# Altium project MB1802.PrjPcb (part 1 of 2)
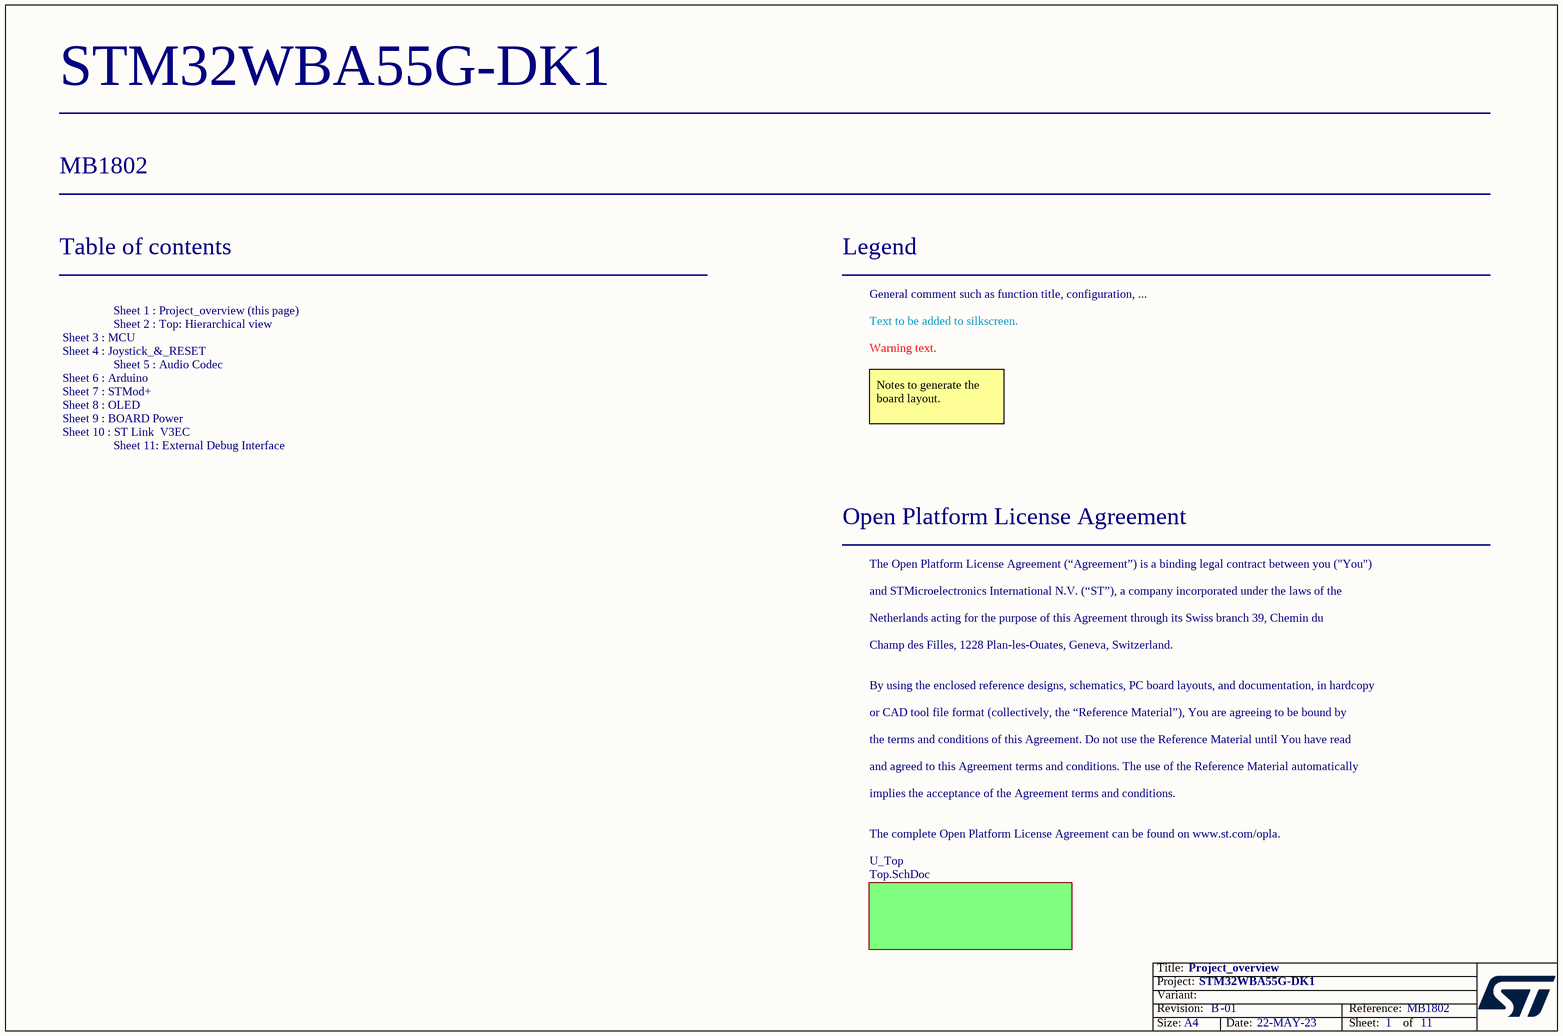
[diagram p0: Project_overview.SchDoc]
Board_Assembly_Revision: 01; Board_Document_Date: 22-MAY-23; Board_Name: STM32WBA55G-DK1; Board_PCB_Revision: B; Board_Reference: MB1802
11 sheets, 218 parts. Net scope: flat (ports and power ports of the same name join across sheets).
Board file: MB1802.PcbDoc
Sheets:
  Project_overview.SchDoc
    U_Top = Top.SchDoc
      U_Board_Power = Board_Power.SchDoc
      U_External_Debug_Interface = External_Debug_Interface.SchDoc
      U_OLED = OLED.SchDoc
      U_STLink_V3EC = STLink_V3EC.SchDoc
      U_MCU = MCU.SchDoc
      U_STMod+ = STMod+.SchDoc
      U_Audio_Codec = Audio_Codec.SchDoc
      U_Joystick_&_Reset = Joystick_&_Reset.SchDoc
      U_Arduino = Arduino.SchDoc

## Sheet Project_overview.SchDoc: Project_overview
size A4; Date: Not used; ApprovedBy: Not used; CheckedBy: Not used; Author: Not used; CompanyName: STMicroelectronics; DrawnBy: Not used; Engineer: Not used; Organization: Not used; Address1: Not used; Address2: Not used; Address3: Not used; Address4: Not used; DocumentNumber: 1; Revision: Not used; SheetNumber: 1; SheetTotal: 11

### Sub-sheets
U_Top = Top.SchDoc: no entries

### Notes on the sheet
- Table of contents
- Legend
- General comment such as function title, configuration, ...
- Text to be added to silkscreen.
- Warning text.
- Notes to generate the board layout.
- Open Platform License Agreement
- The Open Platform License Agreement (“Agreement”) is a binding legal contract between you ("You")
- and STMicroelectronics International N.V. (“ST”), a company incorporated under the laws of the
- Netherlands acting for the purpose of this Agreement through its Swiss branch 39, Chemin du
- Champ des Filles, 1228 Plan-les-Ouates, Geneva, Switzerland.
- Sheet 1 : Project_overview (this page)
  Sheet 2 : Top: Hierarchical view
  Sheet 3 : MCU
  Sheet 4 : Joystick_&_RESET
  Sheet 5 : Audio Codec
  Sheet 6 : Arduino
  Sheet 7 : STMod+
  Sheet 8 : OLED
  Sheet 9 : BOARD Power
  Sheet 10 : ST Link  V3EC
  Sheet 11: External Debug Interface
- By using the enclosed reference designs, schematics, PC board layouts, and documentation, in hardcopy
- or CAD tool file format (collectively, the “Reference Material”), You are agreeing to be bound by
- the terms and conditions of this Agreement. Do not use the Reference Material until You have read
- and agreed to this Agreement terms and conditions. The use of the Reference Material automatically
- implies the acceptance of the Agreement terms and conditions.
- The complete Open Platform License Agreement can be found on www.st.com/opla.

## Sheet Top.SchDoc: Top
size A4; Date: Not used; ApprovedBy: Not used; CheckedBy: Not used; Author: Not used; CompanyName: STMicroelectronics; DrawnBy: Not used; Engineer: Not used; Organization: Not used; Address1: Not used; Address2: Not used; Address3: Not used; Address4: Not used; DocumentNumber: Not used; Revision: Not used; SheetNumber: 2; SheetTotal: 11
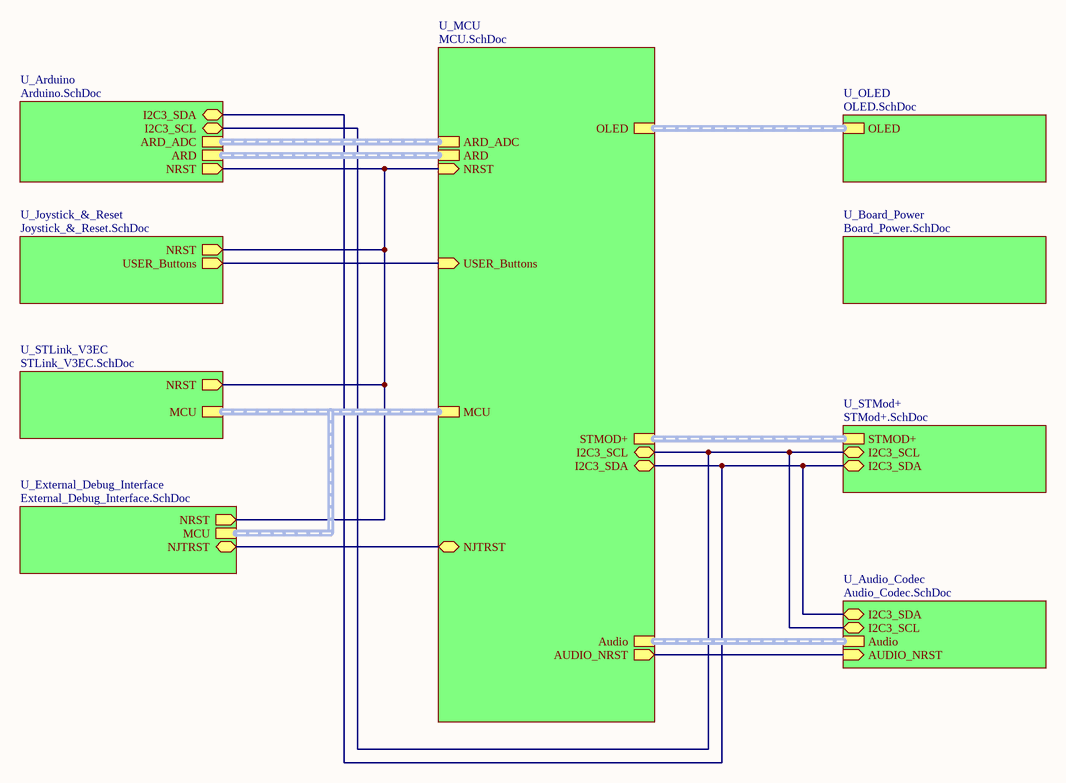
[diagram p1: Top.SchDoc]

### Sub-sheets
U_Arduino = Arduino.SchDoc: NRST (out), I2C3_SDA (bidir), I2C3_SCL (bidir), ARD (harness ARD), ARD_ADC (harness ARD_ADC)
U_Audio_Codec = Audio_Codec.SchDoc: Audio (harness Audio), I2C3_SDA (bidir), I2C3_SCL (bidir), AUDIO_NRST (in)
U_Board_Power = Board_Power.SchDoc: no entries
U_External_Debug_Interface = External_Debug_Interface.SchDoc: MCU (harness MCU), NRST (out), NJTRST (bidir)
U_Joystick_&_Reset = Joystick_&_Reset.SchDoc: NRST (out), USER_Buttons (out)
U_MCU = MCU.SchDoc: Audio (harness Audio), ARD_ADC (harness ARD_ADC), ARD (harness ARD), MCU (harness MCU), STMOD+ (harness STMOD+), OLED (harness OLED), I2C3_SDA (bidir), I2C3_SCL (bidir), USER_Buttons (in), NRST (in), AUDIO_NRST (out), NJTRST (bidir)
U_OLED = OLED.SchDoc: OLED (harness OLED)
U_STLink_V3EC = STLink_V3EC.SchDoc: MCU (harness MCU), NRST (out)
U_STMod+ = STMod+.SchDoc: STMOD+ (harness STMOD+), I2C3_SDA (bidir), I2C3_SCL (bidir)

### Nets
(unnamed): sheet U_External_Debug_Interface/NRST, sheet U_STLink_V3EC/NRST, sheet U_MCU/NRST, sheet U_Joystick_&_Reset/NRST, sheet U_Arduino/NRST
(unnamed): sheet U_External_Debug_Interface/NJTRST, sheet U_MCU/NJTRST  [a separate net that carries the same name]
(unnamed): sheet U_MCU/I2C3_SDA, sheet U_STMod+/I2C3_SDA, sheet U_Audio_Codec/I2C3_SDA, sheet U_Arduino/I2C3_SDA  [a separate net that carries the same name]
(unnamed): sheet U_MCU/I2C3_SCL, sheet U_STMod+/I2C3_SCL, sheet U_Audio_Codec/I2C3_SCL, sheet U_Arduino/I2C3_SCL  [a separate net that carries the same name]
(unnamed): sheet U_MCU/USER_Buttons, sheet U_Joystick_&_Reset/USER_Buttons  [a separate net that carries the same name]
(unnamed): sheet U_MCU/AUDIO_NRST, sheet U_Audio_Codec/AUDIO_NRST  [a separate net that carries the same name]

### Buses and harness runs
harness sheet U_Arduino/ARD = sheet U_MCU/ARD
harness sheet U_Arduino/ARD_ADC = sheet U_MCU/ARD_ADC
harness sheet U_Audio_Codec/Audio = sheet U_MCU/Audio
harness sheet U_External_Debug_Interface/MCU = sheet U_MCU/MCU = sheet U_STLink_V3EC/MCU
harness sheet U_MCU/OLED = sheet U_OLED/OLED
harness sheet U_MCU/STMOD+ = sheet U_STMod+/STMOD+

## Sheet Board_Power.SchDoc: Board_Power
size A4; Date: Not used; ApprovedBy: Not used; CheckedBy: Not used; Author: Not used; CompanyName: STMicroelectronics; DrawnBy: Not used; Engineer: Not used; Organization: Not used; Address1: Not used; Address2: Not used; Address3: Not used; Address4: Not used; DocumentNumber: Not used; Revision: Not used; SheetNumber: 9; SheetTotal: 11
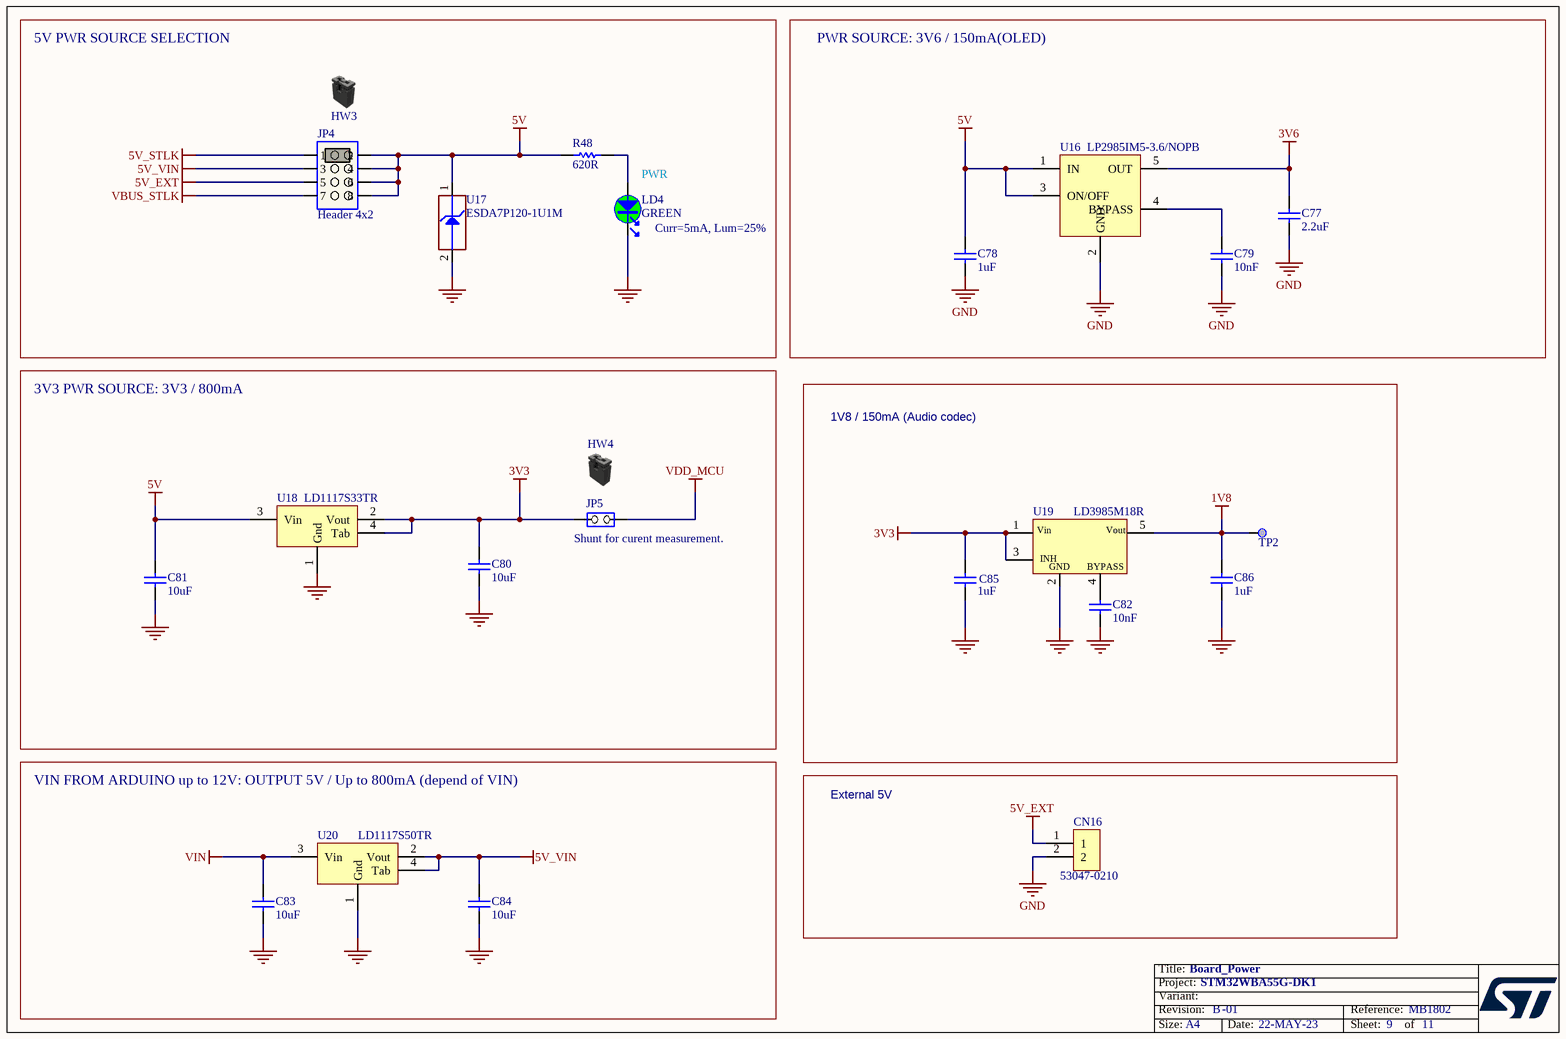
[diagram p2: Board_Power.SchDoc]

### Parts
C77  value 2.2uF  [C0603]  (hidden comment: Capacitor)
C78  value 1uF  [C0603]  (hidden comment: Capacitor)
C79  value 10nF  [C0402]  (hidden comment: Capacitor)
C80  value 10uF  [C0603]  (hidden comment: Capacitor)
C81  value 10uF  [C0603]  (hidden comment: Capacitor)
C82  value 10nF  [C0402]  (hidden comment: Capacitor)
C83  value 10uF  [C0603]  (hidden comment: Capacitor)
C84  value 10uF  [C0603]  (hidden comment: Capacitor)
C85  value 1uF  [C0402]  (hidden comment: Capacitor)
C86  value 1uF  [C0402]  (hidden comment: Capacitor)
CN16  Manufacturer_Part_Number: 53047-0210  [CON_MOLEX_53047-0210]  (hidden comment: Header 2x1)
HW3  (no value)  (mechanical)
HW4  Shunt Black 2.54mm  (value not drawn)  (mechanical)
JP4  value Header 4x2  [CON_SAMTEC_TSW-104-07-X-D]  (hidden comment: Jumper_Header 4x2 Fitted 1-2)
JP5  value Shunt for curent measurement.  [CON_SAMTEC_TSW-102-07-G-S]  (hidden comment: Jumper_Header 2x1)
LD4  value GREEN  [LED_0603_OSRAM_LG-Q396-PS-35_GREEN_1A2K_H0P4]
R48  value 620R  [R0402]
TP2  Test Point  [TP_SMD_0-3MM]  (value not drawn)  (no BOM)
U16  LP2985IM5-3.6/NOPB  [REG_SOT23-5L]
U17  value ESDA7P120-1U1M  [ESD_QFN1610_2N_1K_2A]  (hidden comment: ESD-TRANSIL)
U18  LD1117S33TR  [REG_SOT223-TAB]
U19  LD3985M18R  [REG_SOT23-5L]
U20  LD1117S50TR  [REG_SOT223-TAB]

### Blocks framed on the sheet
5V PWR SOURCE SELECTION: HW3 JP4 LD4 R48 U17
PWR SOURCE: 3V6 / 150mA(OLED): C77-C79 U16
3V3 PWR SOURCE: 3V3 / 800mA: C80 C81 HW4 JP5 U18
1V8 / 150mA (Audio codec): C82 C85 C86 TP2 U19
External 5V: CN16

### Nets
1V8: C86.2 TP2.1 U19.5(Vout)
3V3: C80.2 C85.2 JP5.2(NO) U18.2(Vout) U18.4(Tab) U19.1(Vin) U19.3(CE)
3V6: C77.1 U16.5(OUT)
5V: C78.1 C81.2 JP4.2 JP4.4 JP4.6 JP4.8 R48.2 U16.1(IN) U16.3(ON/OFF) U17.1(IO1) U18.3(Vin)
5V_EXT: CN16.1 JP4.5
5V_STLK: JP4.1
5V_VIN: C84.2 JP4.3 U20.2(Vout) U20.4(Tab)
GND: C77.2 C78.2 C79.2 C80.1 C81.1 C82.1 C83.1 C84.1 C85.1 C86.1 CN16.2 LD4.2 U16.2(GND) U17.2(GND) U18.1(Gnd) U19.2(GND) U20.1(Gnd)
VBUS_STLK: JP4.7
VDD_MCU: JP5.1(COMMON)  [project net V1]
VIN: C83.2 U20.3(Vin)
NetC79_1: C79.1 U16.4(BYPASS)
NetC82_2: C82.2 U19.4(BYPASS)
NetLD4_1: LD4.1 R48.1

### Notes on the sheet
- (near LD4) PWR
- (near LD4) Curr=5mA, Lum=25%
- VIN FROM ARDUINO up to 12V: OUTPUT 5V / Up to 800mA (depend of VIN)

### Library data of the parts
C77 = MCD-00654: Capacitor,2.2uF,16V, X5R,10%,0603,YAGEO; Manufacturer_Part_Number: CC0603KRX5R7BB225; Provided_By: SUBCO
C78 = MCD-00010: Capacitor, MLCC, 1uF, 16V, X5R, 10%, 0603, T=0,8mm; Manufacturer_Part_Number: CC0603KRX5R7BB105; Manufacturer: YAGEO; Provided_By: SUBCO; Initial_Board_Reference: MB1274; Item Type: Item; Path: ws/MCD_ApplicationBoards/Lists/MCDPARTSdatabase
C79 = MCD-00011: Capacitor, MLCC, 10nF, 16V, X7R, 10%, 0402, T=0.5mm; Manufacturer_Part_Number: CC0402KRX7R7BB103; Manufacturer: YAGEO; Provided_By: SUBCO
C80 C81 C83 C84 = MCD-00099: Capacitor, MLCC, 10uF, 10V, X5R, 10%, 0603, T=0,8mm; Manufacturer_Part_Number: GRM188R61A106KE69D; Manufacturer: MURATA; Provided_By: SUBCO; Initial_Board_Reference: MB1262; Item Type: Item; Path: ws/MCD_ApplicationBoards/Lists/MCDPARTSdatabase
C82 = MCD-00011: Capacitor, MLCC, 10nF, 16V, X7R, 10%, 0402, T=0.5mm; Manufacturer_Part_Number: CC0402KRX7R7BB103; Manufacturer: YAGEO; ECCN_US: EAR99; ECCN_EU: NEC; Provided_By: SUBCO
C85 C86 = MCD-01722: Capacitor, 1uF, 10V, X5R, 10%, 0402, T=0.5mm; Manufacturer_Part_Number: CC0402KRX5R6BB105; Manufacturer: YAGEO; Provided_By: SUBCO
CN16 = MCD-00655: Header, 2x1, 1.25mm, VR, TH, T=2.25mm/2.3mm; BMS_Part_Number: 9083002; Part_Type: Connector; Part_Preference: Recommended; Manufacturer: MOLEX; Order_Code_RS: 279-9213; Component_Country_Of_Origin: Unknown; ShowFields: YES; ID: 3091
HW3 = MCD-00043: SHUNT 2.54mm BLACK; Part_Type: Mechanical; Manufacturer_Part_Number: SNT-100-BK-G; Manufacturer: SAMTEC; Provided_By: Subcon; Initial_Board_Reference: MB1274
HW4 = MCD-00043: SHUNT 2.54mm BLACK; Manufacturer_Part_Number: SNT-100-BK-G; Manufacturer: SAMTEC; Part_Type: Mechanical; Provided_By: Subcon; Initial_Board_Reference: MB1274
JP4 = MCD-00686: Header, 4x2, 2.54mm, VR, TH, T=5.84mm/2.54mm; Part_Type: Connector; Part_Preference: Recommended; Manufacturer: SAMTEC; Manufacturer_Part_Number: TSW-104-07-G-D; Order_Code_RS: 161-2260; Component_Country_Of_Origin: China, Costa Rica, Malaysia, United States, Vietnam; ShowFields: YES; ID: 3062
JP5 = MCD-00045: Header, 2x1, 2,54mm, VR, TH, Height 5.84mm/2.54mm; Part_Type: Connector; Manufacturer_Part_Number: TSW-102-07-x-S; Manufacturer: SAMTEC; Provided_By: Subcon; Initial_Board_Reference: MB1274; Remark: 3D KO: BZ: 40098
LD4 = MCD-00588: LED Green, 0603 SMD, Forward Voltage Typ=2V, Max=2.5V; Part_Type: Display; Manufacturer_Part_Number: LG Q396-PS-35; Manufacturer: OSRAM OPTO SEMICONDUCTORS; Alternate_Manufacturer_Part_Number: VLMTG1300-GS08; Alternate_Manufacturer: VISHAY SEMICONDUCTOR OPTO DIVISION; Provided_By: Subcon; Initial_Board_Reference: MB1331
R48 = MCD-00499: Resistor,620R,0402,1%,1/16W; Manufacturer_Part_Number: RC0402FR-07620RL; Manufacturer: YAGEO; Provided_By: Subcon
TP2 = MCD-00630: Test Point 0.3mm; Part_Type: Mechanical
U16 = MCD-01030: LDO VOLTAGE REGULATOR, 3.6V, 150mA, 5-SOT-23, FULL REEL; Part_Type: IC; Manufacturer: TEXAS INSTRUMENTS; Provided_By: SUBCO
U17 = MCD-01026: High power transient voltage suppressor; Part_Type: Diode; Manufacturer: STMICROELECTRONICS; Provided_By: SUBCO with ST control; Initial_Board_Reference: MB1378; Remark: Footprint moved fromROU lib: DFN105P160X60-2N to global-lib: ESD_QFN1610_2N_1K_2A; Item Type: Item; Path: ws/MCD_ApplicationBoards/Lists/MCDPARTSdatabase
U18 = MCD-00089: LOW DROP FIXED AND ADJUSTABLE POSITIVE VOLTAGE REGULATORS (3.3 Volts); Part_Type: IC; Manufacturer: STMICROELECTRONICS; BMS_Part_Number: 9176186; Provided_By: SUBCO with ST control
U19 = MCD-00078: Ultra low drop-low noise BiCMOS voltage, regulators low ESR capacitors compatible; Part_Type: IC; Manufacturer: STMICROELECTRONICS; BMS_Part_Number: 9176159; ECCN_US: EAR99; ECCN_EU: NEC; Provided_By: SUBCO with ST control
U20 = MCD-00088: IC REG LDO 5V 0.8A SOT223; Manufacturer: STMICROELECTRONICS; ECCN_US: EAR99; ECCN_EU: NEC; Provided_By: Subcon; Initial_Board_Reference: MB1274

## Sheet External_Debug_Interface.SchDoc: External_Debug_Interface
size A4; Date: Not used; ApprovedBy: Not used; CheckedBy: Not used; Author: Not used; CompanyName: STMicroelectronics; DrawnBy: Not used; Engineer: Not used; Organization: Not used; Address1: Not used; Address2: Not used; Address3: Not used; Address4: Not used; DocumentNumber: Not used; Revision: Not used; SheetNumber: 11; SheetTotal: 11
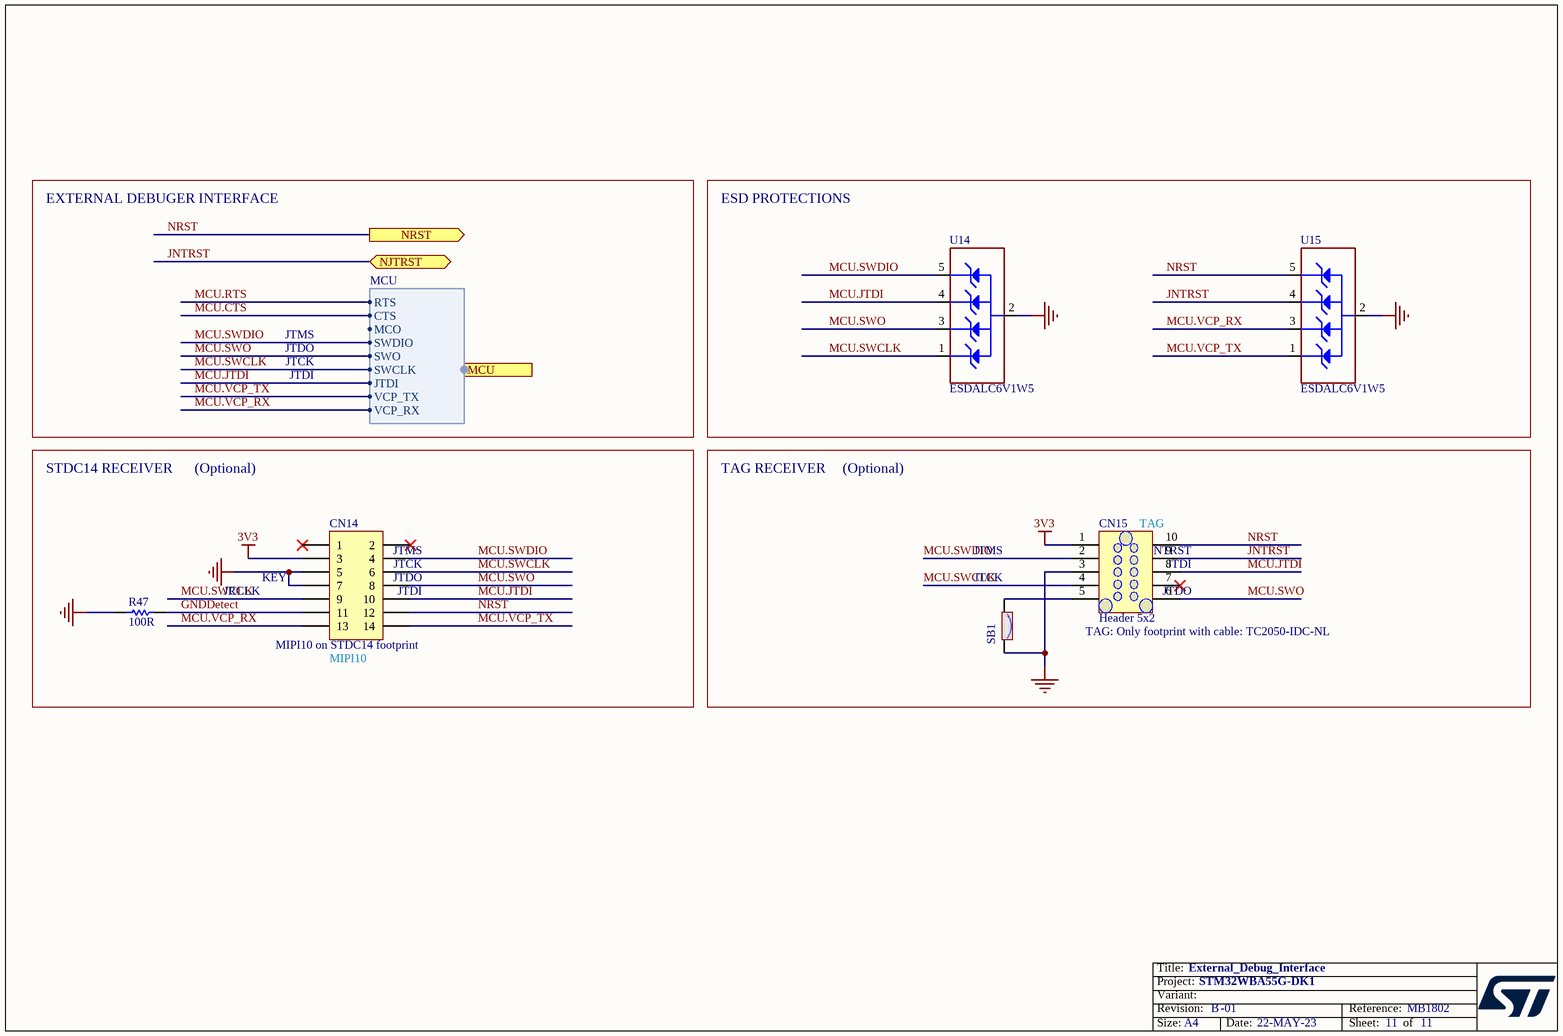
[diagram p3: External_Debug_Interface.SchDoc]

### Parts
CN14  value MIPI10 on STDC14 footprint  [CON_STDC14_Receiver_MEDIUM_WITH_MIPI10_3D]  (hidden comment: Header 7x2)
CN15  value Header 5x2  [CON_TAG-C_TC2050-IDC-NL]  (hidden comment: Tag-10-C)  (no BOM)
R47  value 100R  [R0402]  (hidden comment: Resistor)
SB1  (no value)  [SOLDER-BRIDGE_R0603-0R]
U14  ESDALC6V1W5  [ESD_SOT323-5L]
U15  ESDALC6V1W5  [ESD_SOT323-5L]

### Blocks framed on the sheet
ESD PROTECTIONS: U14 U15

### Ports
MCU (harness MCU), NJTRST (bidir), NRST (out)

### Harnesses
MCU: MCO, SWDIO, SWO, VCP_TX, SWCLK, VCP_RX, JTDI, CTS, RTS

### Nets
3V3: CN14.3 CN15.1
GND: CN14.5 CN14.7 CN15.3 R47.1 SB1.2 U14.2(GND) U15.2(GND)
GNDDetect: CN14.11 R47.2
JNTRST: CN15.9 U15.4(IO3) ; port NJTRST
MCU.JTDI: CN14.10 CN15.8 U14.4(IO3) ; port MCU.JTDI  [project net ARD.D5_TIM]
MCU.SWCLK: CN14.6 CN14.9 CN15.4 U14.1(IO1) ; port MCU.SWCLK
MCU.SWDIO: CN14.4 CN15.2 U14.5(IO4) ; port MCU.SWDIO
MCU.SWO: CN14.8 CN15.6 U14.3(IO2) ; port MCU.SWO  [project net ARD.D3_TIM]
MCU.VCP_RX: CN14.13 U15.3(IO2) ; port MCU.VCP_RX
MCU.VCP_TX: CN14.14 U15.1(IO1) ; port MCU.VCP_TX
NRST: CN14.12 CN15.10 U15.5(IO4) ; port NRST
NetCN15_5: CN15.5 SB1.1

Not connected (* = marked no-connect by the designer): CN14 1* 2*; CN15 7*

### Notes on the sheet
- EXTERNAL DEBUGER INTERFACE
- JTMS
- JTDO
- JTCK
- JTDI
- STDC14 RECEIVER
- (Optional)
- TAG RECEIVER
- (near CN14) KEY
- (near CN14) JTCK
- (near CN14) JTMS
- (near CN14) JTDO
- (near SB1) JTCK
- (near CN15) TAG
- (near CN15) JTDI
- (near CN15) JNTRST
- (near CN14) JRCLK
- (near CN14) JTDI
- (near CN15) TAG: Only footprint with cable: TC2050-IDC-NL
- (near CN15) JTDO
- (near CN14) MIPI10

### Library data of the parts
CN14 = MCD-01226: Header 5x2, 1.27mm, Dual row, Straight, Surface mount, vertical male connector. 3.05mm lead. Mates with FFSD connector. Footprint compatible with FTSH-107-01-L-DV,-K,-A,-P,-ES (STDC14 MEDIUM); Manufacturer_Part_Number: FTSH-105-01-L-DV-K; Manufacturer: SAMTEC; Provided_By: Subcon; Initial_Board_Reference: MCD16-052
CN15 = MCD-00031: Header_Plug-of-nails, 5x2, 1.27mm, No legs; Part_Type: Connector; Part_Preference: Recommended; ShowFields: YES; ID: 2486
R47 = MCD-00067: Resistor, 100R, 0402, +/- 1%, 1/16W; Part_Preference: Recommended; Manufacturer: YAGEO; Manufacturer_Part_Number: RC0402FR-07100RL; Component_Country_Of_Origin: China; ShowFields: YES; ID: 2527
SB1 = MCD-00071: Solder Bridge ON; Part_Type: Mechanical; Provided_By: Subcon; Initial_Board_Reference: mb1274
U14 U15 = MCD-00136: Dual Transil array for ESD protection; BMS_Part_Number: 9151112; Part_Type: Diode; Part_Preference: Recommended; Manufacturer: STMICROELECTRONICS; Manufacturer_HQ_COO: EU; Component_Country_Of_Origin: China

## Sheet OLED.SchDoc: OLED
size A4; Date: Not used; ApprovedBy: Not used; CheckedBy: Not used; Author: Not used; CompanyName: STMicroelectronics; DrawnBy: Not used; Engineer: Not used; Organization: Not used; Address1: Not used; Address2: Not used; Address3: Not used; Address4: Not used; DocumentNumber: Not used; Revision: Not used; SheetNumber: 8; SheetTotal: 11
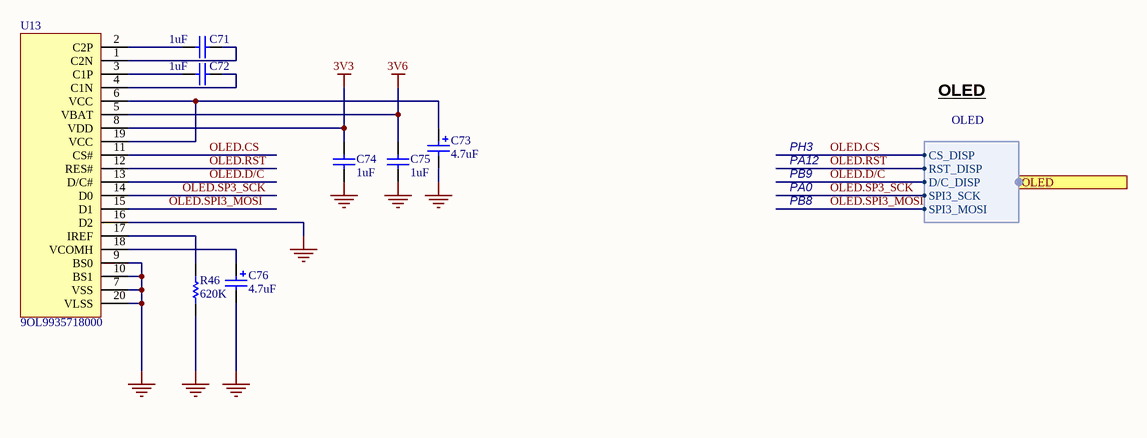
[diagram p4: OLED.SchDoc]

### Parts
C71  value 1uF  [C0603]
C72  value 1uF  [C0603]
C73  value 4.7uF  [CPOL_TAJ-A_1206_H180]  (hidden comment: ​Footprint CPOL_TAJ-A_1206_H180)
C74  value 1uF  [C0603]
C75  value 1uF  [C0603]
C76  value 4.7uF  [CPOL_TAJ-A_1206_H180]  (hidden comment: ​Footprint CPOL_TAJ-A_1206_H180)
R46  value 620K  [R0603]
U13  value 9OL9935718000  [OLED_RITDISPLAY_9OL9935718000]  (hidden comment: OLED_RITDISPLAY_9OL9935718000)

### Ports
OLED (harness OLED)

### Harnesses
OLED: CS_DISP, RST_DISP, D/C_DISP, SPI3_SCK, SPI3_MOSI

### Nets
3V3: C74.1 U13.8(VDD)
3V6: C75.1 U13.5(VBAT)
GND: C73.2 C74.2 C75.2 C76.2 R46.1 U13.7(VSS) U13.9(BS0) U13.10(BS1) U13.16(D2) U13.20(VLSS)
OLED.CS: U13.11(CS#) ; port OLED.CS_DISP
OLED.D/C: U13.13(D/C#) ; port OLED.D/C_DISP  [project net ARD.D12_SPI3_MISO]
OLED.RST: U13.12(RES#) ; port OLED.RST_DISP
OLED.SP3_SCK: U13.14(D0) ; port OLED.SPI3_SCK  [project net ARD.D13_SPI3_SCK]
OLED.SPI3_MOSI: U13.15(D1) ; port OLED.SPI3_MOSI  [project net ARD.D11_TIM_SPI3_MOSI]
NetC71_1: C71.1 U13.2(C2P)
NetC71_2: C71.2 U13.1(C2N)
NetC72_1: C72.1 U13.3(C1P)
NetC72_2: C72.2 U13.4(C1N)
NetC73_1: C73.1 U13.6(VCC) U13.19(VCC)
NetC76_1: C76.1 U13.18(VCOMH)
NetR46_2: R46.2 U13.17(IREF)

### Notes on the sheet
- OLED
- PH3
- PA12
- PB8
- PA0
- PB9

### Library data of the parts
C71 C72 C74 C75 = MCD-00010: Capacitor, MLCC, 1uF, 16V, X5R, 10%, 0603, T=0,8mm; Manufacturer_Part_Number: CC0603KRX5R7BB105; Manufacturer: YAGEO; Provided_By: Subcon; Initial_Board_Reference: MB1274
C73 C76 = MCD-01043: Capacitor, Tantalum, 4.7µF, 25V, 10%, 1206; Manufacturer_Part_Number: 293D475X9025A2TE3; Manufacturer: VISHAY; Provided_By: Subcon; Initial_Board_Reference: MB1378
R46 = MCD-00506: Resistor,620K,0603,1%,1/10W; Manufacturer_Part_Number: RC0603FR-07620KL; Manufacturer: YAGEO; Provided_By: Subcon
U13 = MCD-01925: 128*64 Dots 20-pin OLED display; Part_Preference: Recommended; Component_Country_Of_Origin: Unknown; ShowFields: YES; ID: 4025

## Sheet STLink_V3EC.SchDoc: STLink_V3EC
size A3; Date: Not used; ApprovedBy: Not used; CheckedBy: Not used; Author: Not used; CompanyName: STMicroelectronics; DrawnBy: Not used; Engineer: Not used; Organization: Not used; Address1: Not used; Address2: Not used; Address3: Not used; Address4: Not used; DocumentNumber: Not used; Revision: Not used; SheetNumber: 10; SheetTotal: 11
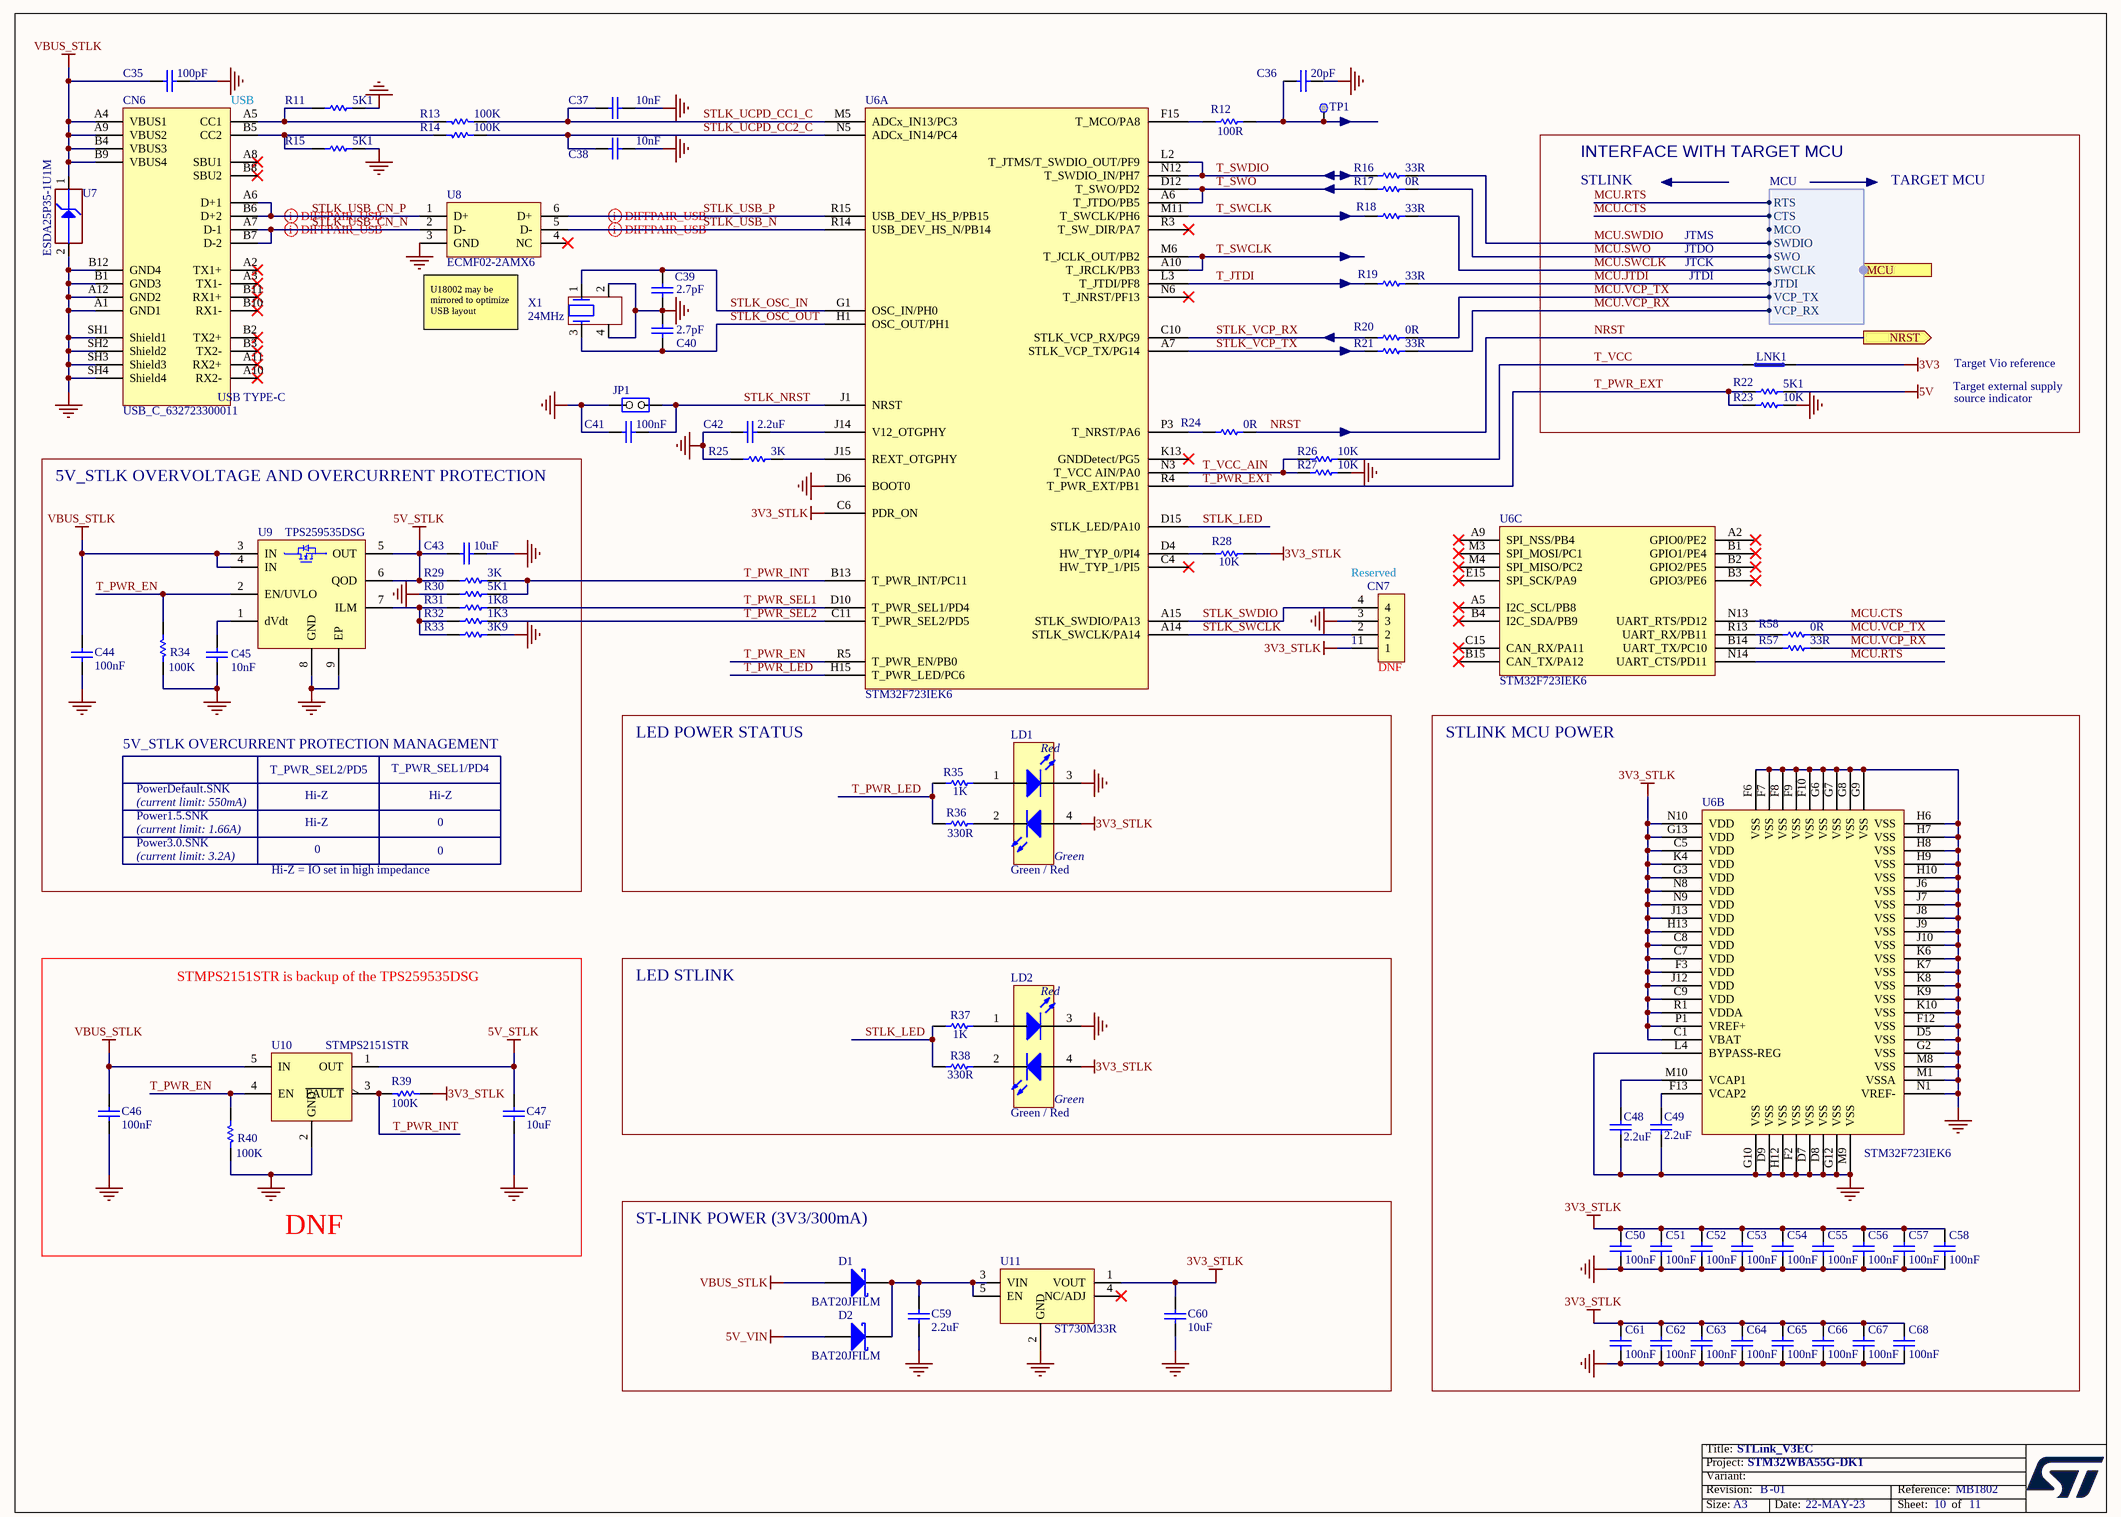
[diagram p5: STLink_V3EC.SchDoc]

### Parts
C35  value 100pF  [C0402]  (hidden comment: Capacitor)
C36  value 20pF  [C0402]  (hidden comment: Capacitor)
C37  value 10nF  [C0402]  (hidden comment: Capacitor)
C38  value 10nF  [C0402]  (hidden comment: Capacitor)
C39  value 2.7pF  [C0402]  (hidden comment: Capacitor)
C40  value 2.7pF  [C0402]  (hidden comment: Capacitor)
C41  value 100nF  [C0402]  (hidden comment: Capacitor)
C42  value 2.2uF  [C0402]  (hidden comment: Capacitor)
C43  value 10uF  [C0603]  (hidden comment: Capacitor)
C44  value 100nF  [C0402]  (hidden comment: Capacitor)
C45  value 10nF  [C0402]  (hidden comment: Capacitor)
C46  value 100nF  [C0402]  (hidden comment: Capacitor)
C47  value 10uF  [C0603]  (hidden comment: Capacitor)
C48  value 2.2uF  [C0402]  (hidden comment: Capacitor)
C49  value 2.2uF  [C0402]  (hidden comment: Capacitor)
C50  value 100nF  [C0402]  (hidden comment: Capacitor)
C51  value 100nF  [C0402]  (hidden comment: Capacitor)
C52  value 100nF  [C0402]  (hidden comment: Capacitor)
C53  value 100nF  [C0402]  (hidden comment: Capacitor)
C54  value 100nF  [C0402]  (hidden comment: Capacitor)
C55  value 100nF  [C0402]  (hidden comment: Capacitor)
C56  value 100nF  [C0402]  (hidden comment: Capacitor)
C57  value 100nF  [C0402]  (hidden comment: Capacitor)
C58  value 100nF  [C0402]  (hidden comment: Capacitor)
C59  value 2.2uF  [C0805]  (hidden comment: Capacitor)
C60  value 10uF  [C0603]  (hidden comment: Capacitor)
C61  value 100nF  [C0402]  (hidden comment: Capacitor)
C62  value 100nF  [C0402]  (hidden comment: Capacitor)
C63  value 100nF  [C0402]  (hidden comment: Capacitor)
C64  value 100nF  [C0402]  (hidden comment: Capacitor)
C65  value 100nF  [C0402]  (hidden comment: Capacitor)
C66  value 100nF  [C0402]  (hidden comment: Capacitor)
C67  value 100nF  [C0402]  (hidden comment: Capacitor)
C68  value 100nF  [C0402]  (hidden comment: Capacitor)
CN6  value USB_C_632723300011  [CON_USB-TYPEC_WE_632723300011]  (hidden comment: USB_TYPE_C_Receptacle)
CN7  Header 4x1  [CON_SAMTEC_TSW-104-07-G-S]  (value not drawn)
D1  value BAT20JFILM  [DIO_SOD323_1A_2K]  (hidden comment: SCHOTTKY_1A_2K)
D2  value BAT20JFILM  [DIO_SOD323_1A_2K]  (hidden comment: SCHOTTKY_1A_2K)
JP1  Jumper_Header 2x1  [CON_SAMTEC_TSW-102-07-G-S]  (value not drawn)
LD1  value Green / Red  [LED_BI-GR_WE-150141SV73110]  (hidden comment: LED_BICOLOR)
LD2  value Green / Red  [LED_BI-GR_WE-150141SV73110]  (hidden comment: LED_BICOLOR)
LNK1  link_200  [LINK200]  (value not drawn)  (no BOM)
R11  value 5K1  [R0402]  (hidden comment: Resistor)
R12  value 100R  [R0402]  (hidden comment: Resistor)
R13  value 100K  [R0402]  (hidden comment: Resistor)
R14  value 100K  [R0402]  (hidden comment: Resistor)
R15  value 5K1  [R0402]  (hidden comment: Resistor)
R16  value 33R  [R0402]  (hidden comment: Resistor)
R17  value 0R  [R0402]  (hidden comment: Resistor)
R18  value 33R  [R0402]  (hidden comment: Resistor)
R19  value 33R  [R0402]  (hidden comment: Resistor)
R20  value 0R  [R0402]  (hidden comment: Resistor)
R21  value 33R  [R0402]  (hidden comment: Resistor)
R22  value 5K1  [R0402]  (hidden comment: Resistor)
R23  value 10K  [R0402]  (hidden comment: Resistor)
R24  value 0R  [R0402]  (hidden comment: Resistor)
R25  value 3K  [R0402]  (hidden comment: Resistor)
R26  value 10K  [R0402]  (hidden comment: Resistor)
R27  value 10K  [R0402]  (hidden comment: Resistor)
R28  value 10K  [R0402]  (hidden comment: Resistor)
R29  value 3K  [R0402]  (hidden comment: Resistor)
R30  value 5K1  [R0402]  (hidden comment: Resistor)
R31  value 1K8  [R0402]  (hidden comment: Resistor)
R32  value 1K3  [R0402]  (hidden comment: Resistor)
R33  value 3K9  [R0402]  (hidden comment: Resistor)
R34  value 100K  [R0402]  (hidden comment: Resistor)
R35  value 1K  [R0402]  (hidden comment: Resistor)
R36  value 330R  [R0402]  (hidden comment: Resistor)
R37  value 1K  [R0402]  (hidden comment: Resistor)
R38  value 330R  [R0402]  (hidden comment: Resistor)
R39  value 100K  [R0402]  (hidden comment: Resistor)
R40  value 100K  [R0402]  (hidden comment: Resistor)
R57  value 33R  [R0402]  (hidden comment: Resistor)
R58  value 0R  [R0402]  (hidden comment: Resistor)
TP1  Test Point  [TP_SMD_1MM]  (value not drawn)  (no BOM)
U6  value STM32F723IEK6  [ICC_UFBGA201_176+25_10X10_P065]  (hidden comment: STLINK-V3EC)  (parts A,B,C of 3)
U7  value ESDA25P35-1U1M  [ESD_QFN1610_2N_1K_2A]  (hidden comment: ESD-TRANSIL)
U8  value ECMF02-2AMX6  [ESD_QFN-6L_1P7X1P5_P050]  (hidden comment: ​)
U9  TPS259535DSG  [ICC_WSON8-EPAD_2X2_P050]
U10  STMPS2151STR  [MOS_SOT23-5L]
U11  ST730M33R  [ICC_SOT23-5L_H1P45]
X1  value 24MHz  [CRY_NX2016SA_4P]  (hidden comment: XTAL_4_PINS)

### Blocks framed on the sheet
INTERFACE WITH TARGET MCU: LNK1 R22 R23
5V_STLK OVERVOLTAGE AND OVERCURRENT PROTECTION: C43-C45 R29-R34 U9
LED POWER STATUS: LD1 R35 R36
STLINK MCU POWER: C48-C58 C61-C68 U6
DNF: C46 C47 R39 R40 U10
LED STLINK: LD2 R37 R38
ST-LINK POWER (3V3/300mA): C59 C60 D1 D2 U11

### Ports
MCU (harness MCU), NRST (out)

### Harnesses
MCU: MCO, SWDIO, SWO, VCP_TX, SWCLK, VCP_RX, JTDI, CTS, RTS

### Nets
3V3: LNK1.1
3V3_STLK: C50.1 C51.1 C52.1 C53.1 C54.1 C55.1 C56.1 C57.1 C58.1 C60.2 C61.1 C62.1 C63.1 C64.1 C65.1 C66.1 C67.1 C68.1 CN7.1 LD1.4(Green_anode) LD2.4(Green_anode) R28.2 R39.1 U6.C1(VBAT) U6.C5(VDD) U6.C6(PDR_ON) U6.C7(VDD) U6.C8(VDD) U6.C9(VDD) U6.F3(VDD) U6.G3(VDD) U6.G13(VDD) U6.H13(VDD) U6.J12(VDD) U6.J13(VDD) U6.K4(VDD) U6.N8(VDD) U6.N9(VDD) U6.N10(VDD) U6.P1(VREF+) U6.R1(VDDA) U11.1(VOUT)
5V: R22.2
5V_STLK: C43.2 C47.2 R29.1 U9.5(OUT) U9.6(QOD) U10.1(OUT)
5V_VIN: D2.1(A)
GND: C35.2 C36.1 C37.2 C38.2 C39.2 C40.1 C41.1 C42.1 C43.1 C44.1 C45.1 C46.1 C47.1 C48.1 C49.1 C50.2 C51.2 C52.2 C53.2 C54.2 C55.2 C56.2 C57.2 C58.2 C59.1 C60.1 C61.2 C62.2 C63.2 C64.2 C65.2 C66.2 C67.2 C68.2 CN6.A1(GND1) CN6.A12(GND2) CN6.B1(GND3) CN6.B12(GND4) CN6.SH1(Shield1) CN6.SH2(Shield2) CN6.SH3(Shield3) CN6.SH4(Shield4) CN7.3 JP1.2(NO) LD1.3(RED_cathode) LD2.3(RED_cathode) R11.2 R15.2 R23.2 R25.2 R27.2 R30.2 R33.2 R34.1 R40.1 U6.D5(VSS) U6.D6(BOOT0) U6.D7(VSS) U6.D8(VSS) U6.D9(VSS) U6.F2(VSS) U6.F6(VSS) U6.F7(VSS) U6.F8(VSS) U6.F9(VSS) U6.F10(VSS) U6.F12(VSS) U6.G2(VSS) U6.G6(VSS) U6.G7(VSS) U6.G8(VSS) U6.G9(VSS) U6.G10(VSS) U6.G12(VSS) U6.H6(VSS) U6.H7(VSS) U6.H8(VSS) U6.H9(VSS) U6.H10(VSS) U6.H12(VSS) U6.J6(VSS) U6.J7(VSS) U6.J8(VSS) U6.J9(VSS) U6.J10(VSS) U6.K6(VSS) U6.K7(VSS) U6.K8(VSS) U6.K9(VSS) U6.K10(VSS) U6.L4(BYPASS-REG) U6.M1(VSSA) U6.M8(VSS) U6.M9(VSS) U6.N1(VREF-) U7.2(GND) U8.3(GND) U9.8(GND) U9.9(EP) U10.2(GND) U11.2(GND) X1.2 X1.4
VBUS_STLK: C35.1 C44.2 C46.2 CN6.A4(VBUS1) CN6.A9(VBUS2) CN6.B4(VBUS3) CN6.B9(VBUS4) D1.1(A) U7.1(IO1) U9.3(IN) U9.4(IN) U10.5(IN)
MCU.CTS: U6.N13(UART_RTS/PD12) ; port MCU.CTS
MCU.JTDI: R19.2 ; port MCU.JTDI  [project net ARD.D5_TIM]
MCU.RTS: U6.N14(UART_CTS/PD11) ; port MCU.RTS
MCU.SWCLK: R18.2 ; port MCU.SWCLK
MCU.SWDIO: R16.2 ; port MCU.SWDIO
MCU.SWO: R17.2 ; port MCU.SWO  [project net ARD.D3_TIM]
MCU.VCP_RX: R21.2 R57.2 ; port MCU.VCP_RX
MCU.VCP_TX: R20.2 R58.2 ; port MCU.VCP_TX
NRST: R24.2 ; port NRST
STLK_LED: R37.2 R38.1 U6.D15(STLK_LED/PA10)
STLK_NRST: C41.2 JP1.1(COMMON) U6.J1(NRST)
STLK_OSC_IN: C39.1 U6.G1(OSC_IN/PH0) X1.1
STLK_OSC_OUT: C40.2 U6.H1(OSC_OUT/PH1) X1.3
STLK_SWCLK: CN7.2 U6.A14(STLK_SWCLK/PA14)
STLK_SWDIO: CN7.4 U6.A15(STLK_SWDIO/PA13)
STLK_UCPD_CC1_C: C37.1 R13.1 U6.M5(ADCx_IN13/PC3)
STLK_UCPD_CC2_C: C38.1 R14.1 U6.N5(ADCx_IN14/PC4)
STLK_USB_CN_N: CN6.A7(D-1) CN6.B7(D-2) U8.2(D-)
STLK_USB_CN_P: CN6.A6(D+1) CN6.B6(D+2) U8.1(D+)
STLK_USB_N: U6.R14(USB_DEV_HS_N/PB14) U8.5(D-)
STLK_USB_P: U6.R15(USB_DEV_HS_P/PB15) U8.6(D+)
STLK_VCP_RX: R20.1 U6.C10(STLK_VCP_RX/PG9)
STLK_VCP_TX: R21.1 U6.A7(STLK_VCP_TX/PG14)
T_JTDI: R19.1 U6.L3(T_JTDI/PF8)
T_PWR_EN: R34.2 R40.2 U6.R5(T_PWR_EN/PB0) U9.2(EN/UVLO) U10.4(EN)
T_PWR_EXT: R22.1 R23.1 U6.R4(T_PWR_EXT/PB1)
T_PWR_INT: R29.2 R30.1 R39.2 U6.B13(T_PWR_INT/PC11) U10.3(~{FAULT})
T_PWR_LED: R35.2 R36.2 U6.H15(T_PWR_LED/PC6)
T_PWR_SEL1: R31.2 U6.D10(T_PWR_SEL1/PD4)
T_PWR_SEL2: R32.2 U6.C11(T_PWR_SEL2/PD5)
T_SWCLK: R18.1 U6.A10(T_JRCLK/PB3) U6.M6(T_JCLK_OUT/PB2) U6.M11(T_SWCLK/PH6)
T_SWDIO: R16.1 U6.L2(T_JTMS/T_SWDIO_OUT/PF9) U6.N12(T_SWDIO_IN/PH7)
T_SWO: R17.1 U6.A6(T_JTDO/PB5) U6.D12(T_SWO/PD2)
T_VCC: LNK1.2 R26.2
T_VCC_AIN: R26.1 R27.1 U6.N3(T_VCC_AIN/PA0)
NetC36_2: C36.2 R12.2 TP1.1
NetC42_2: C42.2 U6.J14(V12_OTGPHY)
NetC45_2: C45.2 U9.1(dVdt)
NetC48_2: C48.2 U6.M10(VCAP1)
NetC49_2: C49.2 U6.F13(VCAP2)
NetC59_2: C59.2 D1.2(K) D2.2(K) U11.3(VIN) U11.5(EN)
NetCN6_A5: CN6.A5(CC1) R11.1 R13.2
NetCN6_B5: CN6.B5(CC2) R14.2 R15.1
NetLD1_1: LD1.1(Red_anode) R35.1
NetLD1_2: LD1.2(Green_cathode) R36.1
NetLD2_1: LD2.1(Red_anode) R37.1
NetLD2_2: LD2.2(Green_cathode) R38.2
NetR12_1: R12.1 U6.F15(T_MCO/PA8)
NetR24_1: R24.1 U6.P3(T_NRST/PA6)
NetR25_1: R25.1 U6.J15(REXT_OTGPHY)
NetR28_1: R28.1 U6.D4(HW_TYP_0/PI4)
NetR31_1: R31.1 R32.1 R33.1 U9.7(ILM)
NetR57_1: R57.1 U6.B14(UART_TX/PC10)
NetR58_1: R58.1 U6.R13(UART_RX/PB11)

Not connected (* = marked no-connect by the designer): CN6 A2(TX1+)* A3(TX1-)* A8(SBU1)* A10(RX2-)* A11(RX2+)* B2(TX2+)* B3(TX2-)* B8(SBU2)* B10(RX1-)* B11(RX1+)*; U6 A2(GPIO0/PE2)* A5(I2C_SCL/PB8)* A9(SPI_NSS/PB4)* B1(GPIO1/PE4)* B2(GPIO2/PE5)* B3(GPIO3/PE6)* B4(I2C_SDA/PB9)* B15(CAN_TX/PA12)* C4(HW_TYP_1/PI5)* C15(CAN_RX/PA11)* E15(SPI_SCK/PA9)* K13(GNDDetect/PG5)* M3(SPI_MOSI/PC1)* M4(SPI_MISO/PC2)* N6(T_JNRST/PF13)* R3(T_SW_DIR/PA7)*; U8 4(NC)*; U11 4(NC/ADJ)*

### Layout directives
differential pair; rule ? : STLK_USB_CN_N, STLK_USB_CN_P, STLK_USB_N, STLK_USB_P

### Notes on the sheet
- (near CN6) USB
- STLINK
- TARGET MCU
- JTMS
- JTDO
- (near U8) U18002 may be mirrored to optimize USB layout
- JTCK
- JTDI
- Target external supply
- Target Vio reference
- source indicator
- (near CN7) Reserved
- (near CN7) 1
- (near CN7) DNF
- 5V_STLK OVERCURRENT PROTECTION MANAGEMENT
- PowerDefault.SNK
- T_PWR_SEL2/PD5
- T_PWR_SEL1/PD4
- (current limit: 550mA)
- (current limit: 1.66A)
- (current limit: 3.2A)
- Power1.5.SNK
- Power3.0.SNK
- Hi-Z
- 0
- Hi-Z = IO set in high impedance
- STMPS2151STR is backup of the TPS259535DSG

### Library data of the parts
C35 = MCD-00205: Capacitor, MLCC, 100pF, 50V, NPO, +/-5%, 0402, T=0.5mm; Part_Preference: Recommended; Manufacturer: YAGEO; Manufacturer_Part_Number: CC0402JRNPO9BN101; Component_Country_Of_Origin: China; ShowFields: YES; ID: 2658
C36 = MCD-00016: Capacitor, MLCC, 20pF, 50V, NPO, +/- 5%, 0402, T=0.5mm; Manufacturer_Part_Number: CC0402JRNPO9BN200; Manufacturer: YAGEO; Part_Preference: Recommended; Component_Country_Of_Origin: China; ShowFields: YES; ID: 2479
C37 C38 C45 = MCD-02198: Capacitor, MLCC, 10nF, 50V, X7R, +/-10%, 0402, T=0.5mm; Part_Preference: Recommended; Manufacturer: YAGEO; Manufacturer_Part_Number: CC0402KRX7R9BB103; Order_Code_RS: 6169644; Component_Country_Of_Origin: China; ShowFields: YES; ID: 4298
C39 C40 = MCD-01774: Capacitor, MLCC, 2.7pF, 50V, NPO, +/-0.1pF, 0402, T=0.5mm; Part_Preference: Recommended; Manufacturer: YAGEO; Manufacturer_Part_Number: CC0402BRNPO9BN2R7; Component_Country_Of_Origin: China
C41 C50-C58 C61-C68 = MCD-00006: Capacitor, MLCC, 100nF, 16V, X7R, +/-10%, 0402, T=0.5mm; Manufacturer_Part_Number: CC0402KRX7R7BB104; Manufacturer: YAGEO; Part_Preference: Recommended; Order_Code_RS: 616-9701; Component_Country_Of_Origin: China; ShowFields: YES; ID: 2474
C42 C48 C49 = MCD-02606: Capacitor, MLCC, 2.2uF, 6.3V, X5R, +/-10%, 0402, T=0.5mm; Part_Preference: Recommended; Manufacturer: YAGEO; Manufacturer_Part_Number: CC0402KRX5R5BB225; Order_Code_RS: 1992205; ShowFields: YES; ID: 4712
C43 C60 = MCD-00099: Capacitor, MLCC, 10uF, 10V, X5R, +/-10%, 0603, T=0.8mm; Part_Preference: Recommended; Manufacturer: MURATA; Manufacturer_Part_Number: GRM188R61A106KE69D; Order_Code_RS: 170-6168; Component_Country_Of_Origin: Japan; ShowFields: YES; ID: 2770
C44 C46 = MCD-02355: Capacitor, MLCC, 100nF, 25V, X7R, +/-10%, 0402, T=0.5mm; Part_Preference: Recommended; Manufacturer: WALSIN; Manufacturer_Part_Number: 0402B104K250CT; Order_Code_RS: 176-3114; Component_Country_Of_Origin: Unknown; ShowFields: YES; ID: 4461
C47 = MCD-00099: Capacitor, MLCC, 10uF, 10V, X5R, +/-10%, 0603, T=0.8mm; Part_Preference: Recommended; Manufacturer: MURATA; Manufacturer_Part_Number: GRM188R61A106KE69D; Order_Code_RS: 170-6168; Component_Country_Of_Origin: Japan
C59 = MCD-02372: Capacitor, MLCC, 2.2uF, 25V, X7R, +/-10%, 0805, T=1,25mm; Manufacturer_Part_Number: GRM21BR71E225KE11L; Manufacturer: MURATA; Part_Preference: Recommended; Component_Country_Of_Origin: Japan; ShowFields: YES; ID: 4478
CN6 = MCD-02273: Connector_USB_TypeC, 24pins, RA, TH, T=1.9mm (USB certified); Part_Preference: Recommended; Manufacturer: WURTH ELEKTRONIK; Manufacturer_Part_Number: 632723300011; Component_Country_Of_Origin: China; ShowFields: YES; ID: 4373
CN7 = MCD-00029: Header, 4x1, 2.54mm, VR, TH, T=5.84mm/2.54mm; Manufacturer_Part_Number: TSW-104-07-G-S; Manufacturer: SAMTEC; Part_Type: Connector; Part_Preference: Recommended; Order_Code_RS: 161-2261; Component_Country_Of_Origin: China, Costa Rica, Malaysia, United States, Vietnam; ShowFields: YES; ID: 2487
D1 D2 = MCD-03011: Signal Schottky Diode, If=1A, Ifsm=5A, Vf =0.54V@1A, Vrrm=23V, Ir = 0.65µA@5V, SOD-323; Part_Preference: Recommended; Manufacturer: STMICROELECTRONICS; Order_Code_RS: 165-7545; ShowFields: YES; ID: 5127
JP1 = MCD-00045: Header, 2x1, 2.54mm, VR, TH, T=5.84mm/2.54mm; Part_Preference: Recommended; Part_Type: Connector; Manufacturer: SAMTEC; Manufacturer_Part_Number: TSW-102-07-G-S; Alternate_Internal_Part_Number: MCD-02390; Order_Code_RS: 155-5312; Component_Country_Of_Origin: China, Costa Rica, Malaysia, United States, Vietnam; ShowFields: YES; ID: 2545
LD1 LD2 = MCD-02631: LED Bicolor, Green/Red, 2V, 20mA,  4-PLCC; Part_Type: Display; Part_Preference: Recommended; Manufacturer: WURTH ELEKTRONIK; Manufacturer_Part_Number: 150141SV73110; Order_Code_RS: 184-6963; Component_Country_Of_Origin: China; ShowFields: YES; ID: 4737
LNK1 = MCD-02777: Track link on PCB 200um width for layout routing. No component assembly and no component in BOM; Part_Type: Misc; Part_Preference: Recommended; Manufacturer: STM; ShowFields: YES; ID: 4889
R11 R15 R22 R30 = MCD-00333: Resistor, 5K1, 0402, +/-1%, 1/16W; Part_Preference: Recommended; Manufacturer: YAGEO; Manufacturer_Part_Number: RC0402FR-075K1L; Component_Country_Of_Origin: China; ShowFields: YES; ID: 2944
R12 = MCD-00067: as R47 on sheet External_Debug_Interface
R13 R14 R34 R39 R40 = MCD-00059: Resistor, 100K, 0402, +/-1%, 1/16W; Manufacturer_Part_Number: RC0402FR-07100KL; Manufacturer: YAGEO; Part_Preference: Recommended; Component_Country_Of_Origin: China; ShowFields: YES; ID: 2533
R16 R18 R19 R21 R57 = MCD-00455: Resistor, 33R, 0402, +/-1%, 1/16W; Part_Preference: Recommended; Manufacturer: YAGEO; Manufacturer_Part_Number: RC0402FR-0733RL; Component_Country_Of_Origin: China; ShowFields: YES; ID: 2821
R17 R20 R24 R58 = MCD-00052: Resistor, 0R, 0402, +/-5%, 1/16W; Part_Preference: Recommended; Manufacturer: YAGEO; Manufacturer_Part_Number: RC0402JR-070RL; Order_Code_RS: 618-5804; Component_Country_Of_Origin: China; ShowFields: YES; ID: 2540
R23 R26-R28 = MCD-00053: Resistor, 10K, 0402, +/-1%, 1/16W; Manufacturer_Part_Number: RC0402FR-0710KL; Manufacturer: YAGEO; BMS_Part_Number: 9131590; Part_Preference: Recommended; Component_Country_Of_Origin: China; ShowFields: YES; ID: 2539
R25 = MCD-00185: Resistor, 3K, 0402, +/-1%, 1/16W; Manufacturer_Part_Number: RC0402FR-073KL; Manufacturer: YAGEO; Part_Preference: Recommended; Component_Country_Of_Origin: China; ShowFields: YES; ID: 2682
R29 = MCD-00185: Resistor, 3K, 0402, +/-1%, 1/16W; Part_Preference: Recommended; Manufacturer: YAGEO; Manufacturer_Part_Number: RC0402FR-073KL; Component_Country_Of_Origin: China; ShowFields: YES; ID: 2682
R31 = MCD-00409: Resistor, 1K8, 0402, +/-1%, 1/16W; Part_Preference: Recommended; Manufacturer: YAGEO; Manufacturer_Part_Number: RC0402FR-071K8L; Component_Country_Of_Origin: China; ShowFields: YES; ID: 2871
R32 = MCD-00381: Resistor, 1K3, 0402, +/-1%, 1/16W; Part_Preference: Recommended; Manufacturer: YAGEO; Manufacturer_Part_Number: RC0402FR-071K3L; Component_Country_Of_Origin: China; ShowFields: YES; ID: 2898
R33 = MCD-02455: Resistor, 3K9, 0402, +/-1%, 1/16W, +/-100ppm/°C; Part_Preference: Recommended; Manufacturer: YAGEO; Manufacturer_Part_Number: RC0402FR-073K9L; Order_Code_RS: 198-7783; Component_Country_Of_Origin: China; ShowFields: YES; ID: 4561
R35 R37 = MCD-02665: Resistor, 1K, 0402, +/-0.1%, 1/16W, +/-25ppm/°C; Part_Preference: Recommended; Manufacturer: YAGEO; Manufacturer_Part_Number: RT0402BRD071KL; Order_Code_RS: 199-1298; ShowFields: YES; ID: 4771
R36 R38 = MCD-00062: Resistor, 330R, 0402, +/-1%, 1/16W; Part_Preference: Recommended; Manufacturer: YAGEO; Manufacturer_Part_Number: RC0402FR-07330RL; Component_Country_Of_Origin: China; ShowFields: YES; ID: 2529
TP1 = MCD-00074: Test Point 1mm; Part_Type: Misc; Part_Preference: Recommended; ShowFields: YES; ID: 2518
U6 = MCD-02706: MCU, Arm Cortex-M7 32-bit MCU, 512KB Flash, 276KB RAM, With Crypto; BMS_Part_Number: 9175300; Part_Type: IC; Part_Preference: Recommended; Manufacturer: STMICROELECTRONICS; Order_Code_RS: 135-8241; ShowFields: YES; ID: 4812
U7 = MCD-01207: High power Transient voltage suppressor:25V/35A EOS and ESD transients protection.; Part_Type: Diode; Manufacturer: STMICROELECTRONICS; BMS_Part_Number: 9179045; Part_Preference: Recommended; Manufacturer_HQ_COO: EU; Component_Country_Of_Origin: China; ShowFields: YES; ID: 3289
U8 = MCD-00649: Common mode filter with ESD protection for USB 2.0 interface; Part_Type: Diode; Manufacturer: STMICROELECTRONICS; BMS_Part_Number: 9151138; Part_Preference: Recommended; Manufacturer_HQ_COO: EU; Component_Country_Of_Origin: China; ShowFields: YES; ID: 3094
U9 = MCD-02532: IC, eFuse with Fast Overvoltage Protection 2.7V to 18V 4A 34mOhm 8-Pin WSON; Part_Preference: Recommended; Manufacturer: TEXAS INSTRUMENTS; ShowFields: YES; ID: 4638
U10 = MCD-00159: 500mA, Enhanced single channel power switches with active high enable pin; Part_Type: IC; Manufacturer: STMICROELECTRONICS; Alternate_Manufacturer_Part_Number: TPS2051C; Alternate_Manufacturer: TEXAS INSTRUMENTS; BMS_Part_Number: 9159009; Provided_By: Subcon; Initial_Board_Reference: MB1264
U11 = MCD-02514: LDO, 3.3V, 300mA, High input voltage: 2.5V to 28V, SOT23-5L; Part_Type: IC; Part_Preference: Recommended; Manufacturer: STMICROELECTRONICS; Component_Country_Of_Origin: Malaysia; ShowFields: YES; ID: 4620
X1 = MCD-01036: Crystal, 24MHz, 6pF, +/-20ppm, 80R, 2x1.6mm; BMS_Part_Number: 9157045; Part_Type: Crystal_Osc; Part_Preference: Recommended; Manufacturer: NDK; Manufacturer_Part_Number: NX2016SA-24MHZ-EXS00A-CS10820; Component_Country_Of_Origin: Unknown

## Sheet MCU.SchDoc: MCU
size A3; Date: Not used; ApprovedBy: Not used; CheckedBy: Not used; Author: Not used; CompanyName: STMicroelectronics; DrawnBy: Not used; Engineer: Not used; Organization: Not used; Address1: Not used; Address2: Not used; Address3: Not used; Address4: Not used; DocumentNumber: Not used; Revision: Not used; SheetNumber: 3; SheetTotal: 11
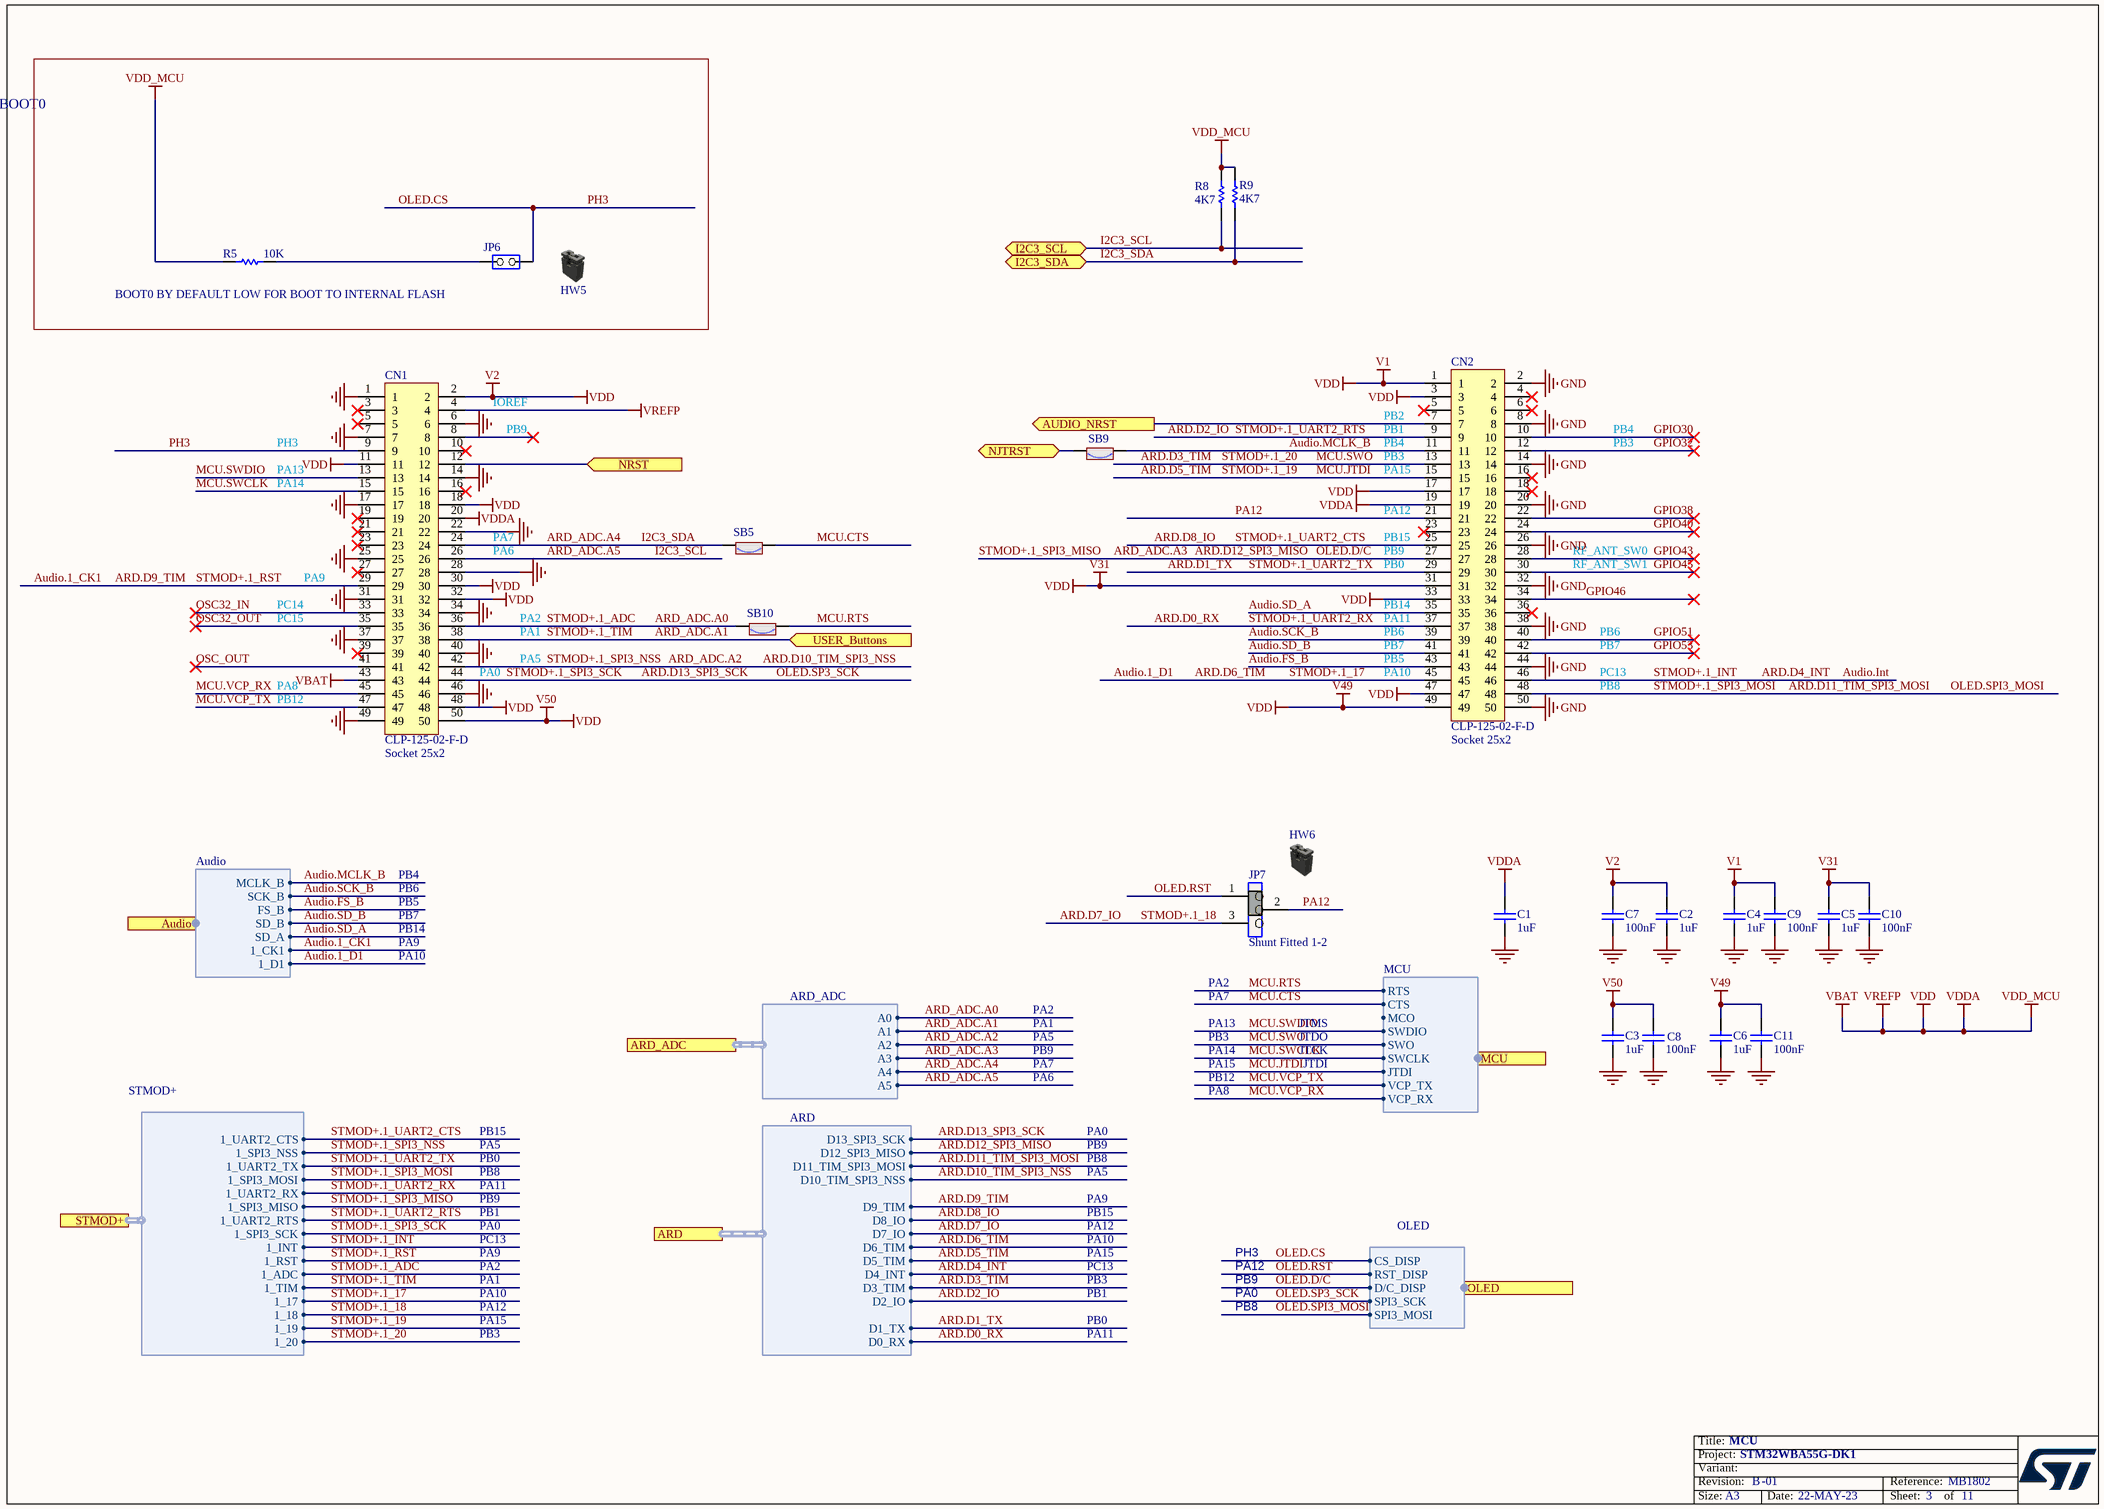
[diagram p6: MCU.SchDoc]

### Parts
C1  value 1uF  [C0805_H0P85]  (hidden comment: Capacitor)
C2  value 1uF  [C0805_H0P85]  (hidden comment: Capacitor)
C3  value 1uF  [C0805_H0P85]  (hidden comment: Capacitor)
C4  value 1uF  [C0805_H0P85]  (hidden comment: Capacitor)
C5  value 1uF  [C0805_H0P85]  (hidden comment: Capacitor)
C6  value 1uF  [C0805_H0P85]  (hidden comment: Capacitor)
C7  value 100nF  [C0402]  (hidden comment: Capacitor)
C8  value 100nF  [C0402]  (hidden comment: Capacitor)
C9  value 100nF  [C0402]  (hidden comment: Capacitor)
C10  value 100nF  [C0402]  (hidden comment: Capacitor)
C11  value 100nF  [C0402]  (hidden comment: Capacitor)
CN1  CLP-125-02-F-D  value Socket 25x2  [CON_SAMTEC_CLP-125-02-F-D]
CN2  CLP-125-02-F-D  value Socket 25x2  [CON_SAMTEC_CLP-125-02-F-D]
HW5  Shunt Black 2.54mm  (value not drawn)  (mechanical)
HW6  Shunt Black 2.54mm  (value not drawn)  (mechanical)
JP6  Jumper_Header 2x1  [CON_SAMTEC_TSW-102-07-G-S]  (value not drawn)
JP7  Shunt Fitted 1-2  [CON_SAMTEC_TSW-103-07-F-S]
R5  value 10K  [R0603]
R8  value 4K7  [R0402]  (hidden comment: Resistor)
R9  value 4K7  [R0402]  (hidden comment: Resistor)
SB5  (no value)  [SOLDER-BRIDGE_R0603-0R]
SB9  (no value)  [SOLDER-BRIDGE_R0603-0R]
SB10  (no value)  [SOLDER-BRIDGE_R0603-0R]

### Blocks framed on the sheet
PH3_BOOT0: HW5 JP6 R5

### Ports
ARD (harness ARD), ARD_ADC (harness ARD_ADC), Audio (harness Audio), AUDIO_NRST (out), I2C3_SCL (bidir), I2C3_SDA (bidir), MCU (harness MCU), NJTRST (bidir), NRST (in), OLED (harness OLED), STMOD+ (harness STMOD+), USER_Buttons (in)

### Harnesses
ARD: D0_RX, D1_TX, D2_IO, D3_TIM, D4_INT, D5_TIM, D6_TIM, D7_IO, D8_IO, D9_TIM, D10_TIM_SPI3_NSS, D11_TIM_SPI3_MOSI, D12_SPI3_MISO, D13_SPI3_SCK
ARD_ADC: A0, A1, A2, A3, A4, A5
MCU: MCO, SWDIO, SWO, VCP_TX, SWCLK, VCP_RX, JTDI, CTS, RTS
STMOD+: 1_UART2_CTS, 1_SPI3_NSS, 1_UART2_TX, 1_SPI3_MOSI, 1_SPI3_MISO, 1_UART2_RTS, 1_ADC, 1_17, 1_18, 1_19, 1_20, 1_UART2_RX, 1_SPI3_SCK, 1_RST, 1_INT, 1_TIM
OLED: CS_DISP, RST_DISP, D/C_DISP, SPI3_SCK, SPI3_MOSI
Audio: MCLK_B, 1_CK1, FS_B, SD_A, SCK_B, SD_B, 1_D1

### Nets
GND: C1.2 C2.1 C3.1 C4.1 C5.1 C6.1 C7.1 C8.2 C9.1 C10.1 C11.1 CN1.1 CN1.6 CN1.7 CN1.14 CN1.17 CN1.22 CN1.25 CN1.28 CN1.31 CN1.34 CN1.37 CN1.40 CN1.46 CN1.49 CN2.2 CN2.8 CN2.14 CN2.20 CN2.26 CN2.32 CN2.38 CN2.44 CN2.50
V1: C1.1 C2.2 C3.2 C4.2 C5.2 C6.2 C7.2 C8.1 C9.2 C10.2 C11.2 CN1.2 CN1.4 CN1.11 CN1.18 CN1.20 CN1.30 CN1.32 CN1.43 CN1.48 CN1.50 CN2.1 CN2.3 CN2.17 CN2.19 CN2.31 CN2.33 CN2.47 CN2.49 R5.1 R8.2 R9.2  [also labelled V2, V31, V49, V50, VBAT, VDD, VDD_MCU, VDDA, VREFP]
ARD.D0_RX: CN2.37 ; port ARD.D0_RX, port STMOD+.1_UART2_RX  [also labelled STMOD+.1_UART2_RX]
ARD.D1_TX: CN2.29 ; port ARD.D1_TX, port STMOD+.1_UART2_TX  [also labelled STMOD+.1_UART2_TX]
ARD.D2_IO: CN2.9 ; port ARD.D2_IO, port STMOD+.1_UART2_RTS  [also labelled STMOD+.1_UART2_RTS]
ARD.D3_TIM: CN2.13 ; port ARD.D3_TIM, port MCU.SWO, port STMOD+.1_20  [also labelled MCU.SWO, STMOD+.1_20]
ARD.D4_INT: CN2.46 ; port ARD.D4_INT, port STMOD+.1_INT  [also labelled Audio.Int, STMOD+.1_INT]
ARD.D5_TIM: CN2.15 ; port ARD.D5_TIM, port MCU.JTDI, port STMOD+.1_19  [also labelled MCU.JTDI, STMOD+.1_19]
ARD.D6_TIM: CN2.45 ; port ARD.D6_TIM, port STMOD+.1_17, port Audio.1_D1  [also labelled Audio.1_D1, STMOD+.1_17]
ARD.D7_IO: JP7.3 ; port ARD.D7_IO, port STMOD+.1_18  [also labelled STMOD+.1_18]
ARD.D8_IO: CN2.25 ; port ARD.D8_IO, port STMOD+.1_UART2_CTS  [also labelled STMOD+.1_UART2_CTS]
ARD.D9_TIM: CN1.29 ; port ARD.D9_TIM, port STMOD+.1_RST, port Audio.1_CK1  [also labelled Audio.1_CK1, STMOD+.1_RST]
ARD.D10_TIM_SPI3_NSS: CN1.42 ; port ARD.D10_TIM_SPI3_NSS, port ARD_ADC.A2, port STMOD+.1_SPI3_NSS  [also labelled ARD_ADC.A2, STMOD+.1_SPI3_NSS]
ARD.D11_TIM_SPI3_MOSI: CN2.48 ; port ARD.D11_TIM_SPI3_MOSI, port STMOD+.1_SPI3_MOSI, port OLED.SPI3_MOSI  [also labelled OLED.SPI3_MOSI, STMOD+.1_SPI3_MOSI]
ARD.D12_SPI3_MISO: CN2.27 ; port ARD.D12_SPI3_MISO, port ARD_ADC.A3, port STMOD+.1_SPI3_MISO, port OLED.D/C_DISP  [also labelled ARD_ADC.A3, OLED.D/C, STMOD+.1_SPI3_MISO]
ARD.D13_SPI3_SCK: CN1.44 ; port ARD.D13_SPI3_SCK, port STMOD+.1_SPI3_SCK, port OLED.SPI3_SCK  [also labelled OLED.SP3_SCK, STMOD+.1_SPI3_SCK]
ARD_ADC.A0: CN1.36 SB10.2 ; port ARD_ADC.A0, port STMOD+.1_ADC  [also labelled STMOD+.1_ADC]
ARD_ADC.A1: CN1.38 ; port USER_Buttons, port ARD_ADC.A1, port STMOD+.1_TIM  [also labelled STMOD+.1_TIM]
ARD_ADC.A4: CN1.24 R9.1 SB5.2 ; port I2C3_SDA, port ARD_ADC.A4  [also labelled I2C3_SDA]
ARD_ADC.A5: CN1.26 R8.1 ; port I2C3_SCL, port ARD_ADC.A5  [also labelled I2C3_SCL]
Audio.FS_B: CN2.43 ; port Audio.FS_B
Audio.MCLK_B: CN2.11 SB9.1 ; port Audio.MCLK_B
Audio.SCK_B: CN2.39 ; port Audio.SCK_B
Audio.SD_A: CN2.35 ; port Audio.SD_A
Audio.SD_B: CN2.41 ; port Audio.SD_B
GPIO30: CN2.10
GPIO32: CN2.12
GPIO38: CN2.22
GPIO40: CN2.24
GPIO43: CN2.28
GPIO45: CN2.30
GPIO46: CN2.34
GPIO51: CN2.40
GPIO53: CN2.42
JNTRST: SB9.2 ; port NJTRST
MCU.CTS: SB5.1 ; port MCU.CTS
MCU.RTS: SB10.1 ; port MCU.RTS
MCU.SWCLK: CN1.15 ; port MCU.SWCLK
MCU.SWDIO: CN1.13 ; port MCU.SWDIO
MCU.VCP_RX: CN1.45 ; port MCU.VCP_RX
MCU.VCP_TX: CN1.47 ; port MCU.VCP_TX
NRST: CN1.12 ; port NRST
OLED.CS: CN1.9 JP6.1(COMMON) ; port OLED.CS_DISP  [also labelled PH3]
OLED.RST: JP7.1 ; port OLED.RST_DISP
OSC32_IN: CN1.33
OSC32_OUT: CN1.35
OSC_OUT: CN1.41
PA12: CN2.21 JP7.2
NetCN2_7: CN2.7 ; port AUDIO_NRST
NetJP6_2: JP6.2(NO) R5.2

Not connected (* = marked no-connect by the designer): CN1 3* 5* 8* 10* 16* 19* 21* 23* 27* 39*; CN2 4* 5* 6* 16* 18* 23* 36*

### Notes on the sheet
- (near R5) BOOT0 BY DEFAULT LOW FOR BOOT TO INTERNAL FLASH
- PH3
- IOREF
- PB9
- (near CN2) PB2
- (near CN2) PB1
- (near CN2) PB4
- PB4
- PB3
- PA13
- PA14
- (near CN2) PB3
- (near CN2) PA15
- (near CN2) PA12
- PA9
- PA7
- PA6
- (near CN2) PB15
- (near CN2) PB9
- (near CN2) PB0
- RF_ANT_SW0
- RF_ANT_SW1
- PC14
- PC15
- PA1
- PA2
- (near CN2) PB14
- (near CN2) PA11
- (near CN2) PB6
- (near CN2) PB7
- PB6
- PB7
- PA8
- PB12
- (near CN1) PA0
- PA5
- (near CN2) PB5
- (near CN2) PA10
- PC13
- PB8
- PB5
- PB14
- PA10
- JTMS
- JTDO
- JTCK
- PA15
- JTDI
- PB15
- PB0
- PA11
- PA0
- PB1
- PA12

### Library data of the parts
C1-C6 = MCD-01550: Capacitor, MLCC, 1uF, 16V, X5R, +/-10%, 0805, T=0.85mm; Part_Preference: Recommended; Manufacturer: YAGEO; Manufacturer_Part_Number: CC0805KRX5R7BB105; Component_Country_Of_Origin: China; ShowFields: YES; ID: 3650
C7-C11 = MCD-02355: as C44 on sheet STLink_V3EC
CN1 CN2 = MCD-02705: Socket, 25x2, 1.27mm, VR, SMD, T=2.29mm; Part_Type: Connector; Part_Preference: Recommended; Manufacturer: SAMTEC; Order_Code_RS: 180-3642; Component_Country_Of_Origin: USA; ShowFields: YES; ID: 4811
HW5 HW6 = MCD-00043: SHUNT 2.54mm BLACK; Part_Type: Mechanical; Manufacturer: SAMTEC; Value: SNT-100-BK-G; Provided_By: SUBCO; Initial_Board_Reference: MB1274; Item Type: Item; Path: ws/MCD_ApplicationBoards/Lists/MCDPARTSdatabase
JP6 = MCD-00045: as JP1 on sheet STLink_V3EC
JP7 = MCD-00684: Header, 3x1, 2,54mm, VR, TH, Height 5.84mm/2.54mm - Shunt Fitted 1-2 by default; Part_Type: Connector; Manufacturer_Part_Number: TSW-103-07-F-S; Manufacturer: SAMTEC; Provided_By: Subcon; Initial_Board_Reference: MB1331
R5 = MCD-00220: Resistor,10K,0603,1%,1/10W; Manufacturer_Part_Number: RC0603FR-0710KL; Manufacturer: YAGEO; Provided_By: Subcon; Initial_Board_Reference: MB1319
R8 R9 = MCD-00065: Resistor,4K7,0402,1%,1/16W; Manufacturer_Part_Number: RC0402FR-074K7L; Manufacturer: YAGEO; Alternate_Manufacturer_Part_Number: RT0402FRE074K7L; Provided_By: SUBCO
SB5 SB9 SB10 = MCD-00071: as SB1 on sheet External_Debug_Interface

## Sheet STMod+.SchDoc: STMod+
size A4; Date: Not used; ApprovedBy: Not used; CheckedBy: Not used; Author: Not used; CompanyName: STMicroelectronics; DrawnBy: Not used; Engineer: Not used; Organization: Not used; Address1: Not used; Address2: Not used; Address3: Not used; Address4: Not used; DocumentNumber: Not used; Revision: Not used; SheetNumber: 7; SheetTotal: 11
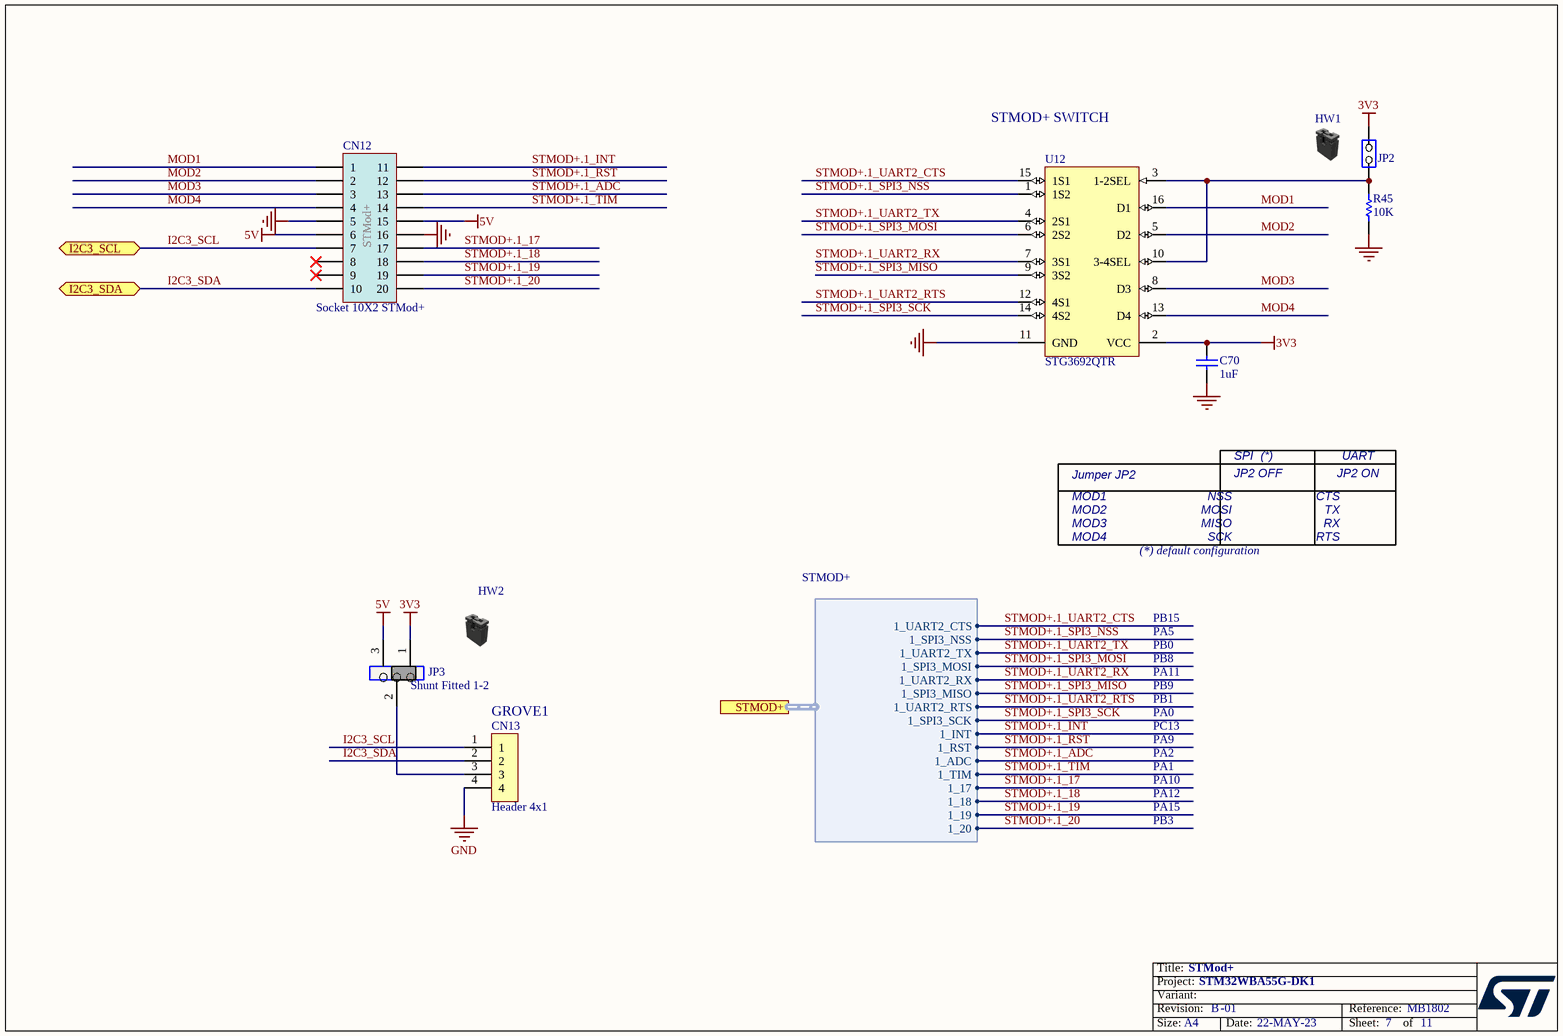
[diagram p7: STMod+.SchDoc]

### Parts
C70  value 1uF  [C0603]  (hidden comment: Capacitor)
CN12  Socket 10X2 STMod+  [CON_SAMTEC_SQT-110-01-F-D-RA__STMOD+]
CN13  Header 4x1  [CON_988-JIUBABA_A2006LF-04A]
HW1  Shunt Black 2.54mm  (value not drawn)  (mechanical)
HW2  Shunt Black 2.54mm  (value not drawn)  (mechanical)
JP2  Jumper_Header 2x1  [CON_SAMTEC_TSW-102-07-G-S]  (value not drawn)
JP3  Shunt Fitted 1-2  [CON_SAMTEC_TSW-103-07-F-S]
R45  value 10K  [R0402]
U12  STG3692QTR  [ICC_UFQFN16-EPAD_2P6X1P8_P040]

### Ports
I2C3_SCL (bidir), I2C3_SDA (bidir), STMOD+ (harness STMOD+)

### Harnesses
STMOD+: 1_UART2_CTS, 1_SPI3_NSS, 1_UART2_TX, 1_SPI3_MOSI, 1_SPI3_MISO, 1_UART2_RTS, 1_ADC, 1_17, 1_18, 1_19, 1_20, 1_UART2_RX, 1_SPI3_SCK, 1_RST, 1_INT, 1_TIM

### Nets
3V3: C70.2 JP2.2(NO) JP3.1 U12.2(VCC)
5V: CN12.6 CN12.15 JP3.3
GND: C70.1 CN12.5 CN12.16 CN13.4 R45.1 U12.11(GND)
I2C3_SCL: CN12.7 CN13.1 ; port I2C3_SCL  [project net ARD_ADC.A5]
I2C3_SDA: CN12.10 CN13.2 ; port I2C3_SDA  [project net ARD_ADC.A4]
MOD1: CN12.1 U12.16(D1)
MOD2: CN12.2 U12.5(D2)
MOD3: CN12.3 U12.8(D3)
MOD4: CN12.4 U12.13(D4)
STMOD+.1_17: CN12.17 ; port STMOD+.1_17  [project net ARD.D6_TIM]
STMOD+.1_18: CN12.18 ; port STMOD+.1_18  [project net ARD.D7_IO]
STMOD+.1_19: CN12.19 ; port STMOD+.1_19  [project net ARD.D5_TIM]
STMOD+.1_20: CN12.20 ; port STMOD+.1_20  [project net ARD.D3_TIM]
STMOD+.1_ADC: CN12.13 ; port STMOD+.1_ADC  [project net ARD_ADC.A0]
STMOD+.1_INT: CN12.11 ; port STMOD+.1_INT  [project net ARD.D4_INT]
STMOD+.1_RST: CN12.12 ; port STMOD+.1_RST  [project net ARD.D9_TIM]
STMOD+.1_SPI3_MISO: U12.9(3S2) ; port STMOD+.1_SPI3_MISO  [project net ARD.D12_SPI3_MISO]
STMOD+.1_SPI3_MOSI: U12.6(2S2) ; port STMOD+.1_SPI3_MOSI  [project net ARD.D11_TIM_SPI3_MOSI]
STMOD+.1_SPI3_NSS: U12.1(1S2) ; port STMOD+.1_SPI3_NSS  [project net ARD.D10_TIM_SPI3_NSS]
STMOD+.1_SPI3_SCK: U12.14(4S2) ; port STMOD+.1_SPI3_SCK  [project net ARD.D13_SPI3_SCK]
STMOD+.1_TIM: CN12.14 ; port STMOD+.1_TIM  [project net ARD_ADC.A1]
STMOD+.1_UART2_CTS: U12.15(1S1) ; port STMOD+.1_UART2_CTS  [project net ARD.D8_IO]
STMOD+.1_UART2_RTS: U12.12(4S1) ; port STMOD+.1_UART2_RTS  [project net ARD.D2_IO]
STMOD+.1_UART2_RX: U12.7(3S1) ; port STMOD+.1_UART2_RX  [project net ARD.D0_RX]
STMOD+.1_UART2_TX: U12.4(2S1) ; port STMOD+.1_UART2_TX  [project net ARD.D1_TX]
NetCN13_3: CN13.3 JP3.2
NetJP2_1: JP2.1(COMMON) R45.2 U12.3(1-2SEL) U12.10(3-4SEL)

Not connected (* = marked no-connect by the designer): CN12 8* 9*

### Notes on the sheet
- STMOD+ SWITCH
- MOD2
- MOD1
- Jumper JP2
- JP2 OFF
- MOSI
- SPI  (*)
- NSS
- JP2 ON
- TX
- UART
- CTS
- MOD3
- MOD4
- (*) default configuration
- MISO
- SCK
- RX
- RTS
- PB15
- PB0
- PA5
- (near CN13) GROVE1
- PB8
- PA11
- PB9
- PA0
- PB1
- PC13
- PA2
- PA1
- PA9
- PA10
- PA12
- PA15
- PB3

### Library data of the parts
C70 = MCD-00010: as C78 on sheet Board_Power
CN12 = MCD-00309: Socket 10x2, 2.00mm, RA, TH, Height 6.35mm/2.29mm; Part_Type: Connector; Manufacturer_Part_Number: SQT-110-01-F-D-RA; Manufacturer: SAMTEC; Provided_By: SubCon; Initial_Board_Reference: MB1311
CN13 = MCD-03083: GROVE female header, SMD, 4 POS, 2.0mm; Part_Type: Connector; Part_Preference: Recommended; Manufacturer: SEEED TECHNOLOGY; Manufacturer_Part_Number: 114020161; Partial_Alternate_Internal_Part_Number: MCD-01741; Order_Code_RS: NA; ShowFields: YES; ID: 5199
HW1 = MCD-00043: as HW4 on sheet Board_Power
HW2 = MCD-00043: as HW5 on sheet MCU
JP2 = MCD-00045: Header, 2x1, 2,54mm, VR, TH, Height 5.84mm/2.54mm; Part_Type: Connector; Manufacturer_Part_Number: TSW-102-07-x-S; Manufacturer: SAMTEC; Value: Shunt not fitted; Provided_By: Subcon; Initial_Board_Reference: MB1274; Remark: 3D KO: BZ: 40098
JP3 = MCD-00684: as JP7 on sheet MCU
R45 = MCD-00053: Resistor,10K,0402,1%,1/16W; Manufacturer_Part_Number: RC0402FR-0710KL; Manufacturer: YAGEO; Provided_By: subcon; Initial_Board_Reference: MB1274
U12 = MCD-00317: Low voltage high bandwidth quad SPDT switch; Part_Type: IC; Manufacturer: STMICROELECTRONICS; Provided_By: SUBCO with ST control; Initial_Board_Reference: MB1311; Item Type: Item; Path: ws/MCD_ApplicationBoards/Lists/MCDPARTSdatabase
